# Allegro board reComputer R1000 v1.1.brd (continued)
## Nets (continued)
GND: C2.2 C3.2 C6.2 C7.2 C8.2 C9.2 C10.2 C11.2 C12.2 C13.2 C14.2 C15.2 C16.2 C19.2 C20.2 C21.2 C22.2 C23.2 C24.2 C28.2 C29.2 C31.2 C32.2 C33.1 C34.1 C35.1 C36.2 C37.2 C38.2 C40.2 C41.2 C42.2 C43.2 C44.2 C45.2 C46.2 C47.2 C48.2 C49.2 C50.2 C51.2 C52.2 C53.2 C54.2 C55.2 C56.2 C57.2 C58.2 C59.2 C60.2 C61.2 C62.2 C63.2 C64.2 C65.2 C66.2 C67.2 C68.2 C69.1 C70.1 C71.1 C72.1 C73.2 C74.2 C75.2 C76.1 C77.2 C78.1 C79.2 C80.2 C81.2 C82.2 C83.2 C84.2 C85.2 C86.2 C87.2 C88.2 C89.2 C90.2 C91.2 C92.2 C93.2 C94.2 C95.2 C96.2 C97.2 C98.2 C99.1 C100.1 C101.1 C102.1 C103.2 C104.2 C105.2 C106.2 C107.2 C108.2 C110.1 C111.2 C112.1 C113.1 C114.1 C115.1 C116.1 C117.2 C118.2 C119.2 C120.2 C121.2 C122.2 C123.2 C124.2 C125.2 C126.2 C127.2 C128.2 C130.2 C131.2 C132.2 C133.2 C136.2 C137.2 C139.2 C140.2 C142.2 C144.2 C145.2 C146.2 C150.2 C151.2 C152.2 C153.2 C159.1 C160.2 C161.2 C163.2 C164.2 C165.2 C166.2 C167.2 C168.2 C169.2 C499.2 C500.2 C501.2 C502.2 C503.2 C504.2 C505.1 C506.1 C507.1 D6.1 D7.1 D8.1 D10.1 D11.1 D12.1 D14.1 D15.1 D16.1 D17.1 D18.1 D19.1 D20.1 D21.1 D22.1 D23.1 D28.1 D30.1 D31.1 D32.1 D33.1 D61.1 D62.1 J2.7 J2.8 J2.9 J2.10 J4.1 J4.2 J4.7 J4.8 J4.13 J4.14 J4.22 J4.23 J4.32 J4.33 J4.42 J4.43 J4.52 J4.53 J4.59 J4.60 J4.65 J4.66 J4.71 J4.74 J4.98 J5.107 J5.108 J5.113 J5.114 J5.119 J5.120 J5.125 J5.126 J5.131 J5.132 J5.137 J5.138 J5.144 J5.150 J5.155 J5.156 J5.161 J5.162 J5.167 J5.168 J5.173 J5.174 J5.179 J5.180 J5.185 J5.186 J5.191 J5.192 J5.197 J5.198 J6.1 J6.4 J9.2 J9.5 J9.8 J9.11 J9.14(UTILITY) J9.17 J10.8 J11.A1 J11.A12 J11.B1 J11.B12 J12.1 J13.8 J14.4 J14.9 J14.15 J14.18 J14.21 J14.26 J14.27 J14.29 J14.34 J14.35 J14.37 J14.40 J14.43 J14.50 J14.53 J14.54 J15.9 J15.15 J15.18 J15.21 J15.26 J15.27 J15.29 J15.34 J15.35 J15.37 J15.40 J15.43 J15.50 J15.53 J15.54 J16.C5 J16.K2 J19.2 J19.4 J19.6 J19.8 J19.10 J19.12 J24.1 J24.4 J24.7 J24.10 J24.13 J24.16 J24.19 J24.SH1 J24.SH2 J24.SH3 J24.SH4 J25.10 J61.1 J61.2 J61.3 J61.5 J61.7 J61.8 J61.10 J61.12 J61.13 J62.1 J62.3 J62.9 J62.15 J62.21 J62.27 J62.33 J62.39 J62.45 J62.51 J62.57 J62.71 J62.73 J62.75 J62.76 J62.77 MH1.1(NC) MH2.1(NC) MH3.1(NC) MH4.1(NC) MH6.1(NC) MH7.1(NC) MH10.1(NC) OSC1.2 Q3.2(S) Q5.2(S) R7.2 R10.1 R12.2 R14.2 R17.1 R19.2 R21.2 R35.2 R37.2 R40.2 R42.1 R45.1 R48.2 R53.1 R54.1 R55.1 R56.1 R57.2 R58.2 R72.2 R73.2 R74.1 R75.1 R92.2 R93.2 R94.2 R95.2 R96.2 R97.2 R108.2 R119.2 R120.2 R123.1 R131.2 R138.2 R147.2 R161.1 R164.2 R173.2 R174.2 R573.2 R632.2 R633.2 R651.1 SW1.1 SW1.3 SW1.4 TP2.1(TP) TP3.1(TP) TP4.1(TP) TP5.1(TP) TP6.1(TP) TP7.1(TP) TP8.1(TP) TP9.1(TP) TP13.1(TP) TP17.1(TP) U1.7 U1.9 U2.7 U2.9 U3.4 U4.29 U4.30 U4.32 U4.34 U4.65 U5.37 U6.1 U7.6 U8.3 U8.8 U9.3 U9.8 U10.3 U10.8 U11.3 U11.8 U12.9 U12.25 U13.1(VSS) U14.4 U15.2 U15.17 U16.4 U17.1 U17.2 U17.3 U17.4 U18.3 U19.4 U19.9 U20.3 U20.8 U21.1(VSS) U22.1 U23.2 U24.2 U24.7 U24.8 U25.7 U25.11 U25.12 U25.13 U26.2 U26.7 U26.8 U27.2 U27.7 U27.8 U28.3(VOUT-) U29.3 U29.8 U30.3 U30.8 U31.2 U32.3 U32.8 U33.5 U34.3 U34.8 X1.2 X1.4 X2.2 X2.4
GND_EARTH: C158.2 C159.2 C505.2 C506.2 C507.2 G1.1 J3.1 J3.2 J3.3 J3.4 J8.S1 J8.S2 J8.S3 J8.S4 J9.20 J9.21 J9.22 J9.23 J10.13 J10.14 J11.S1 J11.S2 J11.S3 J11.S4 J18.13 J18.14 J25.S1 J25.S2 MH11.1(NC) MH12.1(NC) MH13.1(NC) MH14.1(NC) R161.2 R632.1 R633.1
GND_ISO: C134.2 C138.2 C141.2 C143.2 D34.1 D36.2 D39.1 D41.2 D44.1 D46.2 D48.1 J21.3 J22.3 J23.3 R123.2 R132.2 R141.2 R149.2 U22.3(VOUT-) U24.9 U24.10 U24.15 U26.9 U26.10 U26.15 U27.9 U27.10 U27.15
VCC_USB1: C76.2 C78.2 C82.1 C83.1 D16.2 FB5.1 U7.8
VCC_USB2: C77.1 C79.1 C84.1 C85.1 D17.2 FB6.2 U7.5(OUTB)
VDD18CORE: C6.1 C14.1 C19.1 U4.15 U4.38
VDD18ETHPLL: C502.1 FB3.1 U4.48
VDD18USBPLL: C501.1 FB3.2 U4.62
VDD33_HUB1: C40.1 C41.1 C43.1 C44.1 C45.1 C46.1 C47.1 C500.1 FB1.2 FB2.1 R41.1 R43.1 R44.1 R50.2 R78.1 R79.1 R80.1 R81.1 U4.19 U4.27 U4.33 U4.39 U4.40 U4.46 U33.8(VCC)
VDD33_HUB2: C59.1 C62.1 C63.1 C64.1 C65.1 C66.1 C67.1 C68.1 C73.1 FB4.2 R51.1 R52.1 R59.1 R60.2 R61.2 R62.2 R63.2 R65.2 R66.2 R67.2 R68.2 U5.5 U5.10 U5.15 U5.23 U5.29 U5.36 U6.4(VCC)
VDD33A_HUB1: C48.1 C49.1 C50.1 C51.1 C52.1 C53.1 C54.1 FB2.2 U4.5 U4.10 U4.49 U4.51 U4.54 U4.57 U4.64
VDD_3V3_PCIE: C166.1 C167.1 C168.1 C169.1 J62.2 J62.4 J62.12 J62.14 J62.16 J62.18 J62.70 J62.72 J62.74 OSC1.1 OSC1.4(VDD) R175.1 R176.2
VDD_3V3_SYS: C13.1 C23.1 C24.1 C30.1 C38.1 C42.1 C58.1 C89.1 C90.1 C91.1 C106.1 C107.1 C110.2 C163.1 C503.1 C504.1 D25.1 D27.1 FB1.1 FB4.1 FB9.1 FB26.2 FB27.2 J13.1 J13.7 L3.2 R38.1 R85.1 R88.1 R89.1 R90.1 R102.1 R113.1 R116.1 R176.1 R532.1 R653.1 R654.1 TP11.1(TP) U3.9(VCC) U12.21(VCC) U17.8 U19.8(VCC)
VDD_5V_OUT: C161.1 D62.2 J19.7 J19.9 J19.11 U31.1(OUT)
VDD_5V_OUT_CTL: R174.1 U12.12 U31.4
VDD_5V_SYS: C10.1 C11.1 C12.1 C17.1 C31.1 C80.1 C81.1 C108.1 C130.1 C131.1 D63.1 FB10.1 J4.77 J4.79 J4.81 J4.83 J4.85 J4.87 L2.2 R33.2 R104.1 R105.1 R652.1 TP10.1(TP) U7.7 U18.5 U23.5
VDD_IN: C7.1 C8.1 C9.1 C20.1 C21.1 C22.1 C162.1 D2.2(C) J2.2 J2.4 J2.6 Q4.1 Q4.2 Q4.3(S3) R8.1 R16.1 R162.1 TP1.1(TP) U1.2(VIN) U2.2(VIN)
VDD_LTE_3V3: C111.1 C115.2 C124.1 C125.1 C126.1 C127.1 J15.2 J15.39 J15.41 J15.52 R116.2 TP31.1(TP) U21.3
VDD_OUT: D61.2 J19.1 J19.3 J19.5 Q4.5 Q4.6 Q4.7 Q4.8 Q4.9
VDD_OUT_CTL: Q5.1 R164.1 U12.11
VDD_RTC: C104.1 C105.1 D27.2(C) D28.2 D29.2(C) TP22.1(TP) U16.8
VDD_UPS: D2.1 J2.1 J2.3 J2.5 Q1.5 Q1.6 Q1.7 Q1.8 Q1.9
CM4_GPIO24: J4.45 TP38.1(TP)
CM4_GPIO26: J4.24 TP39.1(TP)
CM4_GPIO27: J4.48 TP40.1(TP)
CM4_GPIO_VREF: C35.2 J4.78 R29.1 R30.1 R31.1 R106.1 R107.1 R177.1 R178.1 TP16.1(TP)
CM4_IIC0_SCL: J24.20 R27.1 R177.2 U19.6 U34.4 U34.7
CM4_IIC0_SDA: J24.21 R28.1 R178.2 U19.5 U34.5 U34.6(NC4)
CM4_IIC5_SCL: J61.9 R24.1 R30.2 R88.2 U12.19
CM4_IIC5_SDA: J61.11 R25.2 R31.2 R89.2 U12.20
CM4_IIC6_SCL: J2.11 J14.30 R23.2 R106.2 U16.6 U17.6
CM4_IIC6_SDA: J2.13 J14.32 R22.1 R107.2 U16.5 U17.5
CM4_SPI1_CE0: J4.49 J13.9
CM4_SPI1_CE1: J4.50 J14.51
CM4_SPI1_MISO: J4.26 J13.11 J14.47
CM4_SPI1_MOSI: J4.27 J13.12 J14.49
CM4_SPI1_SCLK: J4.25 J13.10 R111.1
CM4_TPM_IRQ: J4.29 J13.2
CM4_UART0_RXD: J4.51 R100.2
CM4_UART0_TXD: D26.2(C) J4.55 R99.2
CM4_UART2_CTS: J4.58 TP35.1(TP)
CM4_UART2_RTS: J4.56 R127.1
CM4_UART2_RXD: J4.35 R126.1
CM4_UART2_TXD: J4.36 R128.1
CM4_UART3_CTS: J4.30 TP36.1(TP)
CM4_UART3_RTS: J4.37 R136.1
CM4_UART3_RXD: J4.34 R134.1 U25.4
CM4_UART3_TXD: J4.54 R137.1 U25.5
CM4_UART4_CTS: J4.44 TP37.1(TP)
CM4_UART4_RTS: J4.38 R145.1
CM4_UART4_RXD: J4.40 R144.1 U25.9
CM4_UART4_TXD: J4.39 R146.1 U25.10
CM4_UPS_DET: J2.12 J4.41 R654.2
DSI1_C_N: J5.187 J24.8 U32.1 U32.10
DSI1_C_P: J5.189 J24.9 U32.2 U32.9
DSI1_D0_N: J5.175 J24.2 U20.1 U20.10
DSI1_D0_P: J5.177 J24.3 U20.2 U20.9
DSI1_D1_N: J5.181 J24.5 U20.4 U20.7
DSI1_D1_P: J5.183 J24.6 U20.5 U20.6(NC4)
DSI1_D2_N: J5.193 J24.11 U32.4 U32.7
DSI1_D2_P: J5.195 J24.12 U32.5 U32.6(NC4)
DSI1_D3_N: J5.194 J24.14 U34.1 U34.10
DSI1_D3_P: J5.196 J24.15 U34.2 U34.9
EECLK: U4.23 U33.2
EECS: R573.1 U4.24 U33.1
EEDI: U4.26 U33.4
EEDO: U4.25 U33.3
EEPROM_WP: R103.2 U12.10
ETHERNET_LED2: J4.17 R155.1
ETHERNET_LED3: J4.15 R160.1
ETHERNET_PAIR0_N: J4.10 T1.3 U29.2 U29.9
ETHERNET_PAIR0_P: J4.12 T1.1 U29.1 U29.10
ETHERNET_PAIR1_N: J4.6 T1.6 U29.5 U29.6(NC4)
ETHERNET_PAIR1_P: J4.4 T1.4 U29.4 U29.7
ETHERNET_PAIR2_N: J4.9 T1.9 U30.2 U30.9
ETHERNET_PAIR2_P: J4.11 T1.7 U30.1 U30.10
ETHERNET_PAIR3_N: J4.5 T1.12(TD4-) U30.5 U30.6(NC4)
ETHERNET_PAIR3_P: J4.3 T1.10 U30.4 U30.7
ETHERNET_RX_N: J10.3 R80.2 U4.53 U11.4 U11.7
ETHERNET_RX_P: J10.6 R81.2 U4.52 U11.5 U11.6(NC4)
ETHERNET_TX_N: J10.1 R78.2 U4.56 U11.1 U11.10
ETHERNET_TX_P: J10.2 R79.2 U4.55 U11.2 U11.9
EXT_RS485_1_A: D36.1 D37.2 J21.1 R125.2
EXT_RS485_1_B: D37.1 D39.2 J21.2 R130.2
EXT_RS485_2_A: D41.1 D42.2 J22.1 R135.2
EXT_RS485_2_B: D42.1 D44.2 J22.2 R140.2
EXT_RS485_3_A: D46.1 D47.2 J23.1 R143.2
EXT_RS485_3_B: D47.1 D48.2 J23.2 R150.2
EXT_VCC_9_36V: C1.1 C2.1 D1.2(C) L18.2 Q1.1 Q1.2 Q1.3(S3) Q2.2(E) R2.1 R3.1 R4.1
GLOBAL_EN: J4.99 U18.4(Y)
HDMI0_5V: C86.1 C87.1 D20.2 F2.1 J9.18
HDMI0_CEC: J5.151 J9.13 U10.1 U10.10
HDMI0_CLK_N: J5.190 L22.3
HDMI0_CLK_N1: J9.12 L22.4 U9.5 U9.6(NC4)
HDMI0_CLK_P: J5.188 L22.2
HDMI0_CLK_P1: J9.10 L22.1 U9.4 U9.7
HDMI0_HOTPLUG: J5.153 J9.19 U10.2 U10.9
HDMI0_SCL: J5.200 J9.15 U10.5 U10.6(NC4)
HDMI0_SDA: J5.199 J9.16 U10.4 U10.7
HDMI0_TX0_N: J5.184 L21.3
HDMI0_TX0_N1: J9.9 L21.4 U9.2 U9.9
HDMI0_TX0_P: J5.182 L21.2
HDMI0_TX0_P1: J9.7 L21.1 U9.1 U9.10
HDMI0_TX1_N: J5.178 L20.3
HDMI0_TX1_N1: J9.6 L20.4 U8.5 U8.6(NC4)
HDMI0_TX1_P: J5.176 L20.2
HDMI0_TX1_P1: J9.4 L20.1 U8.4 U8.7
HDMI0_TX2_N: J5.172 L19.3
HDMI0_TX2_N1: J9.3 L19.4 U8.2 U8.9
HDMI0_TX2_P: J5.170 L19.2
HDMI0_TX2_P1: J9.1 L19.1 U8.1 U8.10
IO_BUZZER_EN: R39.1 U12.15
ISO_5V: R117.1 U22.4
LORA_3V3: C112.2 C113.2 C114.2 C117.1 C118.1 C119.1 J14.2 J14.24 J14.39 J14.41 J14.52 R113.2 TP30.1(TP)
LORAWAN_SX1262_CS: J14.25 U12.1
LORAWAN_SX1262_RST: J14.10 U12.2
LORAWAN_SX1302_RST: R110.2 U12.3
LTE_RESET: R109.2 U12.4
NEXTRST: J4.100 R46.1
NLNKA_LED: R83.1 U4.21
NPIBOOT: J4.93 J6.2
NPWR_LED: J4.95 J25.1
NSPD_LED: R84.1 U4.22
PCIE_CLK_N: J5.112 J62.53
PCIE_CLK_NREQ: J5.102 J62.52
PCIE_CLK_P: J5.110 J62.55
PCIE_NRST: J5.109 J62.50
PCIE_RX_N: J5.118 J62.41
PCIE_RX_P: J5.116 J62.43
PCIE_TX_N: J5.124 J62.47
PCIE_TX_P: J5.122 J62.49
PCIE_USIM_PRESE: J15.44 J16.K1 R114.2
PL_NLED: J4.21 J25.2
POE_12V: C144.1 C145.1 C146.1 D1.1 TP34.1(TP) U28.1 U28.2
POE_IN_N: C148.2 C149.2 D50.1 D51.2 D52.2 L16.1
POE_IN_N1: C147.1 L16.4 U28.7 U28.8
POE_IN_P: C149.1 D51.1 D52.1 L15.2
POE_IN_P1: C147.2 L16.3 U28.5 U28.6
RS485_1_A: R124.2 R125.1 R129.1 U24.12
RS485_1_B: R129.2 R130.1 R132.1 U24.13
RS485_2_A: R133.2 R135.1 R139.1 U26.12
RS485_2_B: R139.2 R140.1 R141.1 U26.13
RS485_3_A: R142.2 R143.1 R148.1 U27.12
RS485_3_B: R148.2 R149.1 R150.1 U27.13
RS485_LED1: J25.6 U25.3
RS485_LED2: J25.7 U25.6
RS485_LED3: J25.8 U25.8
RS485_POWER_EN: R122.1 U12.14
RTC_INT: C109.1 R104.2 U16.3
RUN_PG: J4.92 R36.2
SD_VDD_OVERRIDE: J4.73 R26.1
TPM_RST: J13.3 U12.5
TRCT: C88.1 J10.4 J10.5 J10.9 J10.12 R82.2
UART2_RXD: R126.2 U24.3 U25.1
UART2_TXD: R128.2 U24.6 U25.2
UART_3V3: C97.1 C100.2 D24.1 R96.1 R98.1 TP21.1(TP) U13.2 U15.1(VIO)
USB1_RST: C55.1 R44.2 R46.2 R64.1 U4.12
USB2_RST: C61.1 R52.2 R59.2 R71.2 U5.26 U6.2
USB2_RST_EN: R71.1 U12.13
USB2_VBUS_EN1: R65.1 R75.2 U5.12 U7.1
USB2_VBUS_EN2: R66.1 R74.2 U5.16 U7.4
USB2_VRCURN1: R60.1 U5.13 U7.2
USB2_VRCURN2: R61.1 U5.17 U7.3
USB_0M: U3.7 U4.58
USB_0P: U3.1 U4.59
USB_1M: U3.6 U14.6
USB_1P: U3.2 U14.2
USB_C_DM: R530.2 U14.5
USB_C_DP: R531.2 U14.3
USB_DET: C60.1 R51.2 U5.27
USB_DM: J5.103 U3.5
USB_DP: J5.105 U3.3
USB_HUB1_DM2: J61.6 U4.1
USB_HUB1_DM3: U4.3 U5.30
USB_HUB1_DP2: J61.4 U4.2
USB_HUB1_DP3: U4.4 U5.31
USB_HUB2_DM1: L4.4 U5.1
USB_HUB2_DM2: L5.2 U5.3
USB_HUB2_DM3: J14.36 U5.6
USB_HUB2_DM4: J15.36 U5.8
USB_HUB2_DP1: L4.1 U5.2
USB_HUB2_DP2: L5.3 U5.4
USB_HUB2_DP3: J14.38 U5.7
USB_HUB2_DP4: J15.38 U5.9
USB_OTG_ID: C37.1 J5.101 R34.2 R35.1 U3.10 U14.10
USB_OTG_ID1: J6.5(COM2) R34.1
USB_TO_UART_DM: U14.7 U15.8
USB_TO_UART_DP: U14.1 U15.7
USBA_GND: J8.A4 J8.B4 R72.1 R73.1
USBC_DM: D23.2 J11.A7 J11.B7 R530.1
USBC_DP: D22.2 J11.A6 J11.B6 R531.1
USER_LED_B: J25.4 U12.8
USER_LED_G: J25.3 U12.7
USER_LED_R: J25.5 U12.6
USIM_1V8: C116.2 R112.1 R114.1 TP29.1(TP) U21.2
USIM_CLK: C123.1 D31.2 J15.12 J16.C3
USIM_DATA: C122.1 D30.2 J15.10 J16.C7 R115.2
USIM_GND: J15.4 R108.1
USIM_RST: C128.1 D32.2 J15.14 J16.C2
USIM_VDD: C120.1 C121.1 D33.2 J15.8 J16.C1 R115.1
VETH_DVDDH: C160.1 FB9.2 J18.10 J18.12 R82.1
N17790331: J4.31 R25.1
N17790840: J4.89(WL_NDISABLE) TP14.1(TP)
N17790854: J4.91 TP15.1(TP)
N18106868: J4.19 TP12.1(TP)
N21083178: D29.1 J12.2 TP23.1(TP)
N21084468: C109.2 R105.2 U18.2
N21116206: F1.1 J1.1 R182.1
N21116211: D4.1 D5.1 D7.2(C) J1.2 R183.2
N21116390: D3.1 D5.2 D6.2(C) F1.2
N21149713: J14.14 TP25.1(TP)
N21149734: J14.16 TP26.1(TP)
N21149896: J14.31 TP27.1(TP)
N21149903: J14.33 TP28.1(TP)
N21150017: J14.45 R111.2
N21187983: D8.2(C) R2.2 R5.1
N21187993: Q2.1 R5.2
N21188161: D9.1 Q2.3
N21188625: C1.2 D9.2(C) Q1.4 R3.2 R7.1
N21206327: C103.1 R101.2 U16.1 X3.2
N21206924: C102.2 R101.1 U16.2(X2) X3.1
N21339151: J14.22 R110.1
N21339355: J15.22 R109.1
N21392725: C36.1 J6.6 R32.1 R33.1
N21411651: C133.1 L11.2 U22.2
N21411770: D34.2(C) R118.2 TP33.1(TP)
N21419586: R127.2 R131.1 U24.4(\\R\E) U24.5
N21629438: C3.1 R4.2
N21664516: R37.1 U3.8
N21891930: C56.1 R47.1 R49.1 X1.1
N21894342: C57.1 R49.2 U4.60(XO) X1.3
N22026897: J18.1 T1.24
N22026906: J18.2 T1.22
N22026915: J18.3 T1.21
N22026957: J18.7 T1.15
N22026966: J18.8 T1.13
N22027038: R153.2 R159.1 T1.14
N22027110: R151.2 R157.1 T1.20
N22027117: R154.2 R158.1 T1.17
N22027433: J18.11(YELC) R155.2
N22027462: J18.9 R160.2
N22028382: R152.2 R156.1 T1.23
N22028488: D52.4 R153.1
N22028491: D52.3(~2) R154.1
N22029929: C148.1 D50.2 L15.1 L16.2
N22030276: D51.4 R151.1
N22030277: D51.3(~2) R152.1
N22038029: C154.1 R156.2
N22038032: C154.2 C155.2 C156.2 C157.2 C158.1
N22038068: C155.1 R157.2
N22038120: C156.1 R158.2
N22038172: C157.1 R159.2
N22078660: J18.6 T1.19
N22078676: J18.5 T1.16
N22078685: J18.4 T1.18
N22567639: C153.1 T1.11
N22567644: C152.1 T1.8
N22567654: C151.1 T1.5
N22567659: C150.1 T1.2
N22666345: R119.1 R122.2 U23.4
N22666568: R120.1 U23.3
N22695835: J14.8 TP24.1(TP)
N22714565: R102.2 R103.1 U17.7(WP)
N23370571: R41.2 U4.11
N23400557: R42.2 U4.63
N23401903: R43.2 U4.41
N23402124: R45.2 U4.50
N23405519: R47.2 U4.61
N23430020: R134.2 U26.3
N23430038: R136.2 R138.1 U26.4(\\R\E) U26.5
N23430129: R137.2 U26.6
N23431044: R144.2 U27.3
N23431062: R145.2 R147.1 U27.4(\\R\E) U27.5
N23431153: R146.2 U27.6
N23449459: J11.A5 R94.1
N23449477: J11.B5 R95.1
N23449775: C98.1 D24.2(C) D25.2(C) U14.9(VCC)
N23449933: D26.1 R98.2 R99.1 U15.5
N23449979: C101.2 U15.6
N23450082: R100.1 U15.4
N23450096: R97.1 U14.8
N23451512: R53.2 U5.28
N23451530: R54.2 U5.22
N23451550: R55.2 U5.24
N23451563: R56.2 U5.25
N23451623: R57.1 U5.11
N23451671: R58.1 U5.35
N23451839: C69.2 C70.2 U5.34
N23451845: R62.1 U5.19
N23451875: C71.2 C72.2 U5.14
N23451879: R63.1 U5.21
N23451944: R69.2 U5.32(XTALOUT)
N23451981: R67.1 U5.18
N23452005: C75.1 R70.2 U5.33 X2.3
N23452009: R68.1 U5.20
N23452027: C74.1 R69.1 R70.1 X2.1
N23452929: FB6.1 J8.B1(VBUS_B)
N23452966: D18.2 J8.B2 L5.1
N23452985: D19.2 J8.B3 L5.4
N23455465: D12.2 R36.1 SW1.2
N23456906: R64.2 U6.3
N23459666: R50.1 U4.28
N23461225: R48.1 U4.44
N23461314: TP19.1(TP) U4.45
N23463209: J10.10 R83.2
N23463212: J10.11(YELC) R84.2
N23463479: TP18.1(TP) U4.20
N23466024: R85.2 U12.18
N23466034: R90.2 U12.22
N23466170: R92.1 U12.23
N23466179: R93.1 U12.24
N23473877: B1.1 D13.2(C) R38.2
N23473909: B1.2(-) D13.1 Q3.3
N23473945: Q3.1 R39.2 R40.1
N23500588: J62.68(SUSCLK(32KHZ) (O)(0/3.3V)) OSC1.3
N23502047: J62.54 R175.2
N23514160: J4.46 R22.2
N23514205: J4.47 R23.1
N23529653: J4.80 R27.2
N23529656: J4.82 R28.2
N23572410: C162.2 Q4.4 R162.2 R163.2
N23572413: Q5.3 R163.1
N23572753: C164.1 C165.1 FB10.2 U31.5
N23578952: R173.1 U31.3
N23579284: C499.1 D3.2(C) D4.2(C) L18.1
N23611485: R12.1 U1.4
N23611490: C15.1 U1.6
N23612078: C5.1 U1.1
N23612081: C5.2 R9.1
N23613464: D10.2(C) L2.1 R9.2 R11.1 U1.8
N23613978: R8.2 R10.2 U1.3
N23614867: C17.2 R13.2 R14.1 U1.5
N23615765: C16.1 R11.2
N23616333: C18.1 U2.1
N23616335: C18.2 R15.1
N23616337: D11.2(C) L3.1 R15.2 R18.1 U2.8
N23616378: R16.2 R17.2 R181.2 U2.3
N23616505: R19.1 U2.4
N23616509: C30.2 R20.2 R21.1 U2.5
N23616593: C28.1 U2.6
N23616615: C29.1 R18.2
N23711005: D15.2 J8.A2 L4.3
N23711301: D14.2 J8.A3 L4.2
N23763799: G1.2 R182.2 R183.1
N23781625: R651.2 U33.6
N23800931: R13.1 R652.2
N23801005: R20.1 R653.2
N23858113: FB26.1 J24.22
N23860408: FB27.1 J25.9
N23869571: D63.2(C) F2.2
N23912708: J4.28 R24.2
N234528750: FB5.2 J8.A1

Pads without a net: J4 16 18 20 57 61 62 63 64 67 68 69 70 72 75 76 94 96 97; J5 104 106 111 115 117 121 123 127 128 129 130 133 134 135 136 139 140 141 142 143 145 146 147 148 149 152 154 157 158 159 160 163 164 165 166 169 171; J6 3; J10 7; J13 4 5 6 13; J14 1 3 5 6 7 11 12 13 17 19 20 23 28 42 44 46 48; J15 1 3 5 6 7 11 13 16 17 19 20 23 24 25 28 30 31 32 33 42 45 46 47 48 49 51; J16 C6; J19 13; J24 17 18; J62 5 6 7 8 10 11 13 17 19 20 22 23 24 25 26 28 29 30 31 32 34 35 36 37 38 40 42 44 46 48 56 58 67 69; U4 6 7 8 9 13 14 16 17 18 31 35 36 37 42 43 47; U12 16 17; U15 10 11 12 13 14 15 16; U16 7; U18 1; U19 1 2 3 7; U24 11 14; U26 11 14; U27 11 14; U28 4; U33 7

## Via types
v1: diameter 0.406, hole 0.203, TOP to BOTTOM, 1791 vias
v2: diameter 0.457, hole 0.203, TOP to BOTTOM, 4 vias

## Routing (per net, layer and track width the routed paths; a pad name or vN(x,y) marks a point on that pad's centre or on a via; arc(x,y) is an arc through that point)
3V3_RS485: length 79.6
  TOP w0.305: C139.1 v1(37.46,56.85) 37.46,57.35 37.37,57.43 U25.14
  LYR3 w0.508: v1(37.46,56.85) 39.96,54.36 39.96,52.64 35.94,48.63 32.46,48.63 31.19,47.36 31.19,43.27 32.77,41.69 32.77,30.59 35.23,28.13 v1(35.23,26.33)
  LYR6 w0.508: v1(62.38,25.34) 62.28,25.23 58.02,25.23 55.73,22.95 49.67,22.95 48.06,24.56 41.65,24.56 39.88,26.33 v1(35.23,26.33)
  BOTTOM w0.305: U27.1 62.69,24.88 62.84,25.03 C142.1 ; C142.1 v1(62.84,25.72) ; C142.1 v1(62.38,25.34) ; U24.1 84.67,24.46 85.07,24.85 C137.1 83.9,25.31 83.7,25.11 v1(83.7,24.19) ; v1(72.64,24.52) 73.43,25.31 C140.1 74.07,24.93 73.71,24.57 U26.1
  vias: v1(62.87,26.78)
5V_ISO_OUT: length 14.3
  TOP w0.305: v1(84.69,15.3) 85.06,14.93 C138.1 ; C141.1 74.04,15.05 v1(73.74,15.35) ; C143.1 62.74,13.15 v1(62.59,13.3) ; R118.1 v1(64.59,17.05)
  TOP w0.508: R124.1 v1(92.36,16.32) ; R133.1 v1(79.83,9.54) ; R142.1 72.8,10.76 72.44,10.4 v1(72.44,9.77)
  BOTTOM w0.305: v1(73.74,15.35) 73.74,14.33 U26.16 ; v1(62.59,13.3) 62.69,13.4 U27.16 ; U24.16 84.69,14.31 v1(84.69,15.3)
  BOTTOM w0.508: v1(92.36,16.32) 94.21,16.32 TP32.1
  vias: v1(66.93,12.97) v1(67.36,12.99) v1(67.82,12.99)
5V_TYPC: length 3
  TOP w0.254: U15.9 v1(39.03,53.69) ; 34.6,54.52 34.92,54.19 U15.3
  TOP w0.508: C99.2 34.31,55.19 v1(34.37,55.13) 34.39,55.11 34.39,54.73 34.6,54.52
  vias: v1(10.7,35.78) v1(11.15,35.78) v1(28.04,37.91) v1(28.07,37.45) v1(28.53,37.91) v1(28.55,37.45) v1(33.89,22.9) v1(33.89,22.39) v1(34.37,22.9) v1(34.37,22.39) v1(60.07,3.16) v1(60.07,2.7) v1(60.51,2.7) v1(61.01,12.66) v1(61.01,12.23) v1(61.45,12.23) v1(61.8,10.12) v1(62.23,10.12) v1(62.23,9.66)
+1.8V_OUT: length 1.4
  TOP w0.203: J4.88 56.6,72.21 v1(56.52,72.12) ; v1(56.16,71.87) 56.2,71.91 J4.90
+3.3V_OUT: length 52.4
  TOP w0.305: v1(59.44,79.84) 59.47,79.88 C32.1 R26.2
  LYR3 w0.305: v1(59.44,79.84) 59.44,78.9 58.06,77.52 v1(58.06,74.87) ; v1(58.02,37.88) 57.69,38.21 57.69,52.06 58.91,53.28 58.91,60.64 57.69,61.86 57.69,66.66 53.72,70.63 53.72,72.55 53.98,72.81 56.9,72.81 57.2,72.5 v1(57.2,72.07)
  BOTTOM w0.254: v1(58.02,37.88) 58.1,37.8 58.1,37.42 R181.1
  BOTTOM w0.305: v1(58.06,74.87) R29.2 57.62,73.29 C33.2 57.23,72.1 v1(57.2,72.07)
GND: length 1120.8
  TOP w0.203: U4.30 47.84,35.87 47.86,35.85 ; 45.39,34.99 45.38,35 45.38,35.33 45.53,35.48 U4.34 46.93,35.48 47.09,35.32 ; 70.08,38.13 70.2,38.25 J5.120 70.2,39.52 70.21,39.52 ; J5.186 v1(57,37.82) ; J5.174 v1(59.4,38.15) ; v1(69.19,42.48) 69,42.29 J5.125 69,40.54 68.99,40.52 ; v1(61.83,41.22) 62.89,41.22 63,41.33 J5.155 63,42.38 ; v1(61.83,41.22) 61.8,41.24 J5.161 61.8,42.57 v1(61.8,42.57) ; v1(61.83,41.22) 60.66,41.22 ; C102.1 8.89,70.24 v1(8.91,70.22) ; J4.7 72.6,74.9 v1(72.6,74.89) ; 67.8,41.06 67.8,41.07 J5.131 67.8,42.52 67.67,42.66 ; J4.43 65.4,76.18 65.48,76.26 65.48,77.3 v1(65,77.79) ; v1(47.27,35.93) 47.09,35.93 46.84,36.18 U4.32 ; 67.19,8.77 68.51,8.77 v1(68.53,8.75) ; J5.107 v1(72.6,42.57) ; 60.66,41.22 60.6,41.27 J5.167 60.6,42.53 ; 60.66,41.22 59.49,41.22 ; v1(72.6,72.05) 72.6,72.05 J4.8 72.6,73.18 72.37,73.42 ; J4.53 v1(63.4,76.44) ; 59.49,41.22 59.4,41.31 J5.173 59.4,42.7 59.39,42.71 ; 59.49,41.22 58.24,41.22 v1(58.2,41.25) ; J5.113 v1(71.4,42.55) ; v1(70.26,43.06) 70.2,43.01 J5.119 70.2,41.41 69.93,41.13 69.9,41.13 ; J4.66 61,72.14 v1(60.99,72.12) ; 54.51,42.63 54.6,42.54 J5.197 54.6,41.32 54.59,41.3 54.67,41.22 55.73,41.22 ; v1(58.2,41.25) J5.179 58.2,42.69 58.22,42.71 ; v1(58.2,41.25) 58.17,41.22 57,41.22 ; v1(58.2,41.25) J5.180 ; 55.73,41.22 55.8,41.29 J5.191 55.8,42.59 55.73,42.66 ; 55.73,41.22 57,41.22 ; v1(69.52,76.47) 69.4,76.35 J4.23 ; 55.76,39.43 55.8,39.39 J5.192 55.8,37.94 55.73,37.87 ; v1(68.2,39.81) 67.8,39.41 J5.132 67.8,38 67.82,37.98 ; J4.71 59.8,75.15 59.84,75.11 ; 64.11,37.87 64.2,37.96 J5.150 ; U12.9 30.65,70.36 v1(30.38,70.62) ; 57,41.22 57,41.3 57,41.3 J5.185 57,42.46 57.08,42.53 v1(57.08,42.63) ; J4.65 61,75.17 v1(61.01,75.16) ; 68.99,37.96 69,37.97 J5.126 69,39.9 v1(69.04,39.94) ; C48.2 58.04,25.46 v1(58.37,25.79) ; v1(66.6,37.35) J5.138 66.6,39.58 ; 65.36,39.66 65.4,39.62 J5.144 65.4,37.76 65.41,37.76 ; X1.2 52.18,25.59 v1(52.17,25.59) ; 60.68,38.13 60.6,38.21 J5.168 ; J4.32 67.8,73.42 66.97,74.26 66.73,74.26 v1(66.58,74.41) ; C49.2 55.47,25.34 R42.1 ; J4.1 73.8,76.35 v1(73.81,76.36) ; U3.4 v1(60.28,31.13) ; v1(62.03,73.29) 62.18,73.29 62.2,73.27 J4.60 ; J5.198 54.6,39.37 54.69,39.46 ; J4.22 69.8,73.42 69.75,73.47 v1(69.7,73.47) ; J4.13 71.4,78.63 MH6.1 ; 66.58,40.88 66.6,40.91 J5.137 66.6,42.71 66.47,42.84 65.1,42.84 v1(65.05,42.79) ; v1(71.38,73.44) 71.4,73.42 J4.14 71.4,71.92 71.38,71.89 ; J4.33 67.4,75.41 67.41,75.4 v1(67.41,75.2) ; v1(61.7,38) 61.8,38.1 J5.162 ; v1(59.44,72.1) 59.4,72.13 J4.74 ; v1(54.36,73.39) 54.6,73.15 J4.98 ; J5.156 63,38.29 v1(62.84,38.13) ; J5.108 72.6,38.25 v1(72.21,37.86) ; J4.59 62.2,75.23 v1(62.13,75.16) ; v1(71.4,37.85) J5.114 ; J4.42 65.8,73.36 65.97,73.52 ; 48.36,35.8 48.34,35.83 U4.29 ; J4.52 63.8,73.22 63.6,73.42 ; J4.2 v1(73.8,72.11)
  TOP w0.254: 36.14,56.87 36.07,56.95 U25.12 ; v1(7.22,69.81) 7.21,69.82 C103.2 ; C55.2 57.51,34.48 57.76,34.22 v1(57.76,33.92) ; U15.2 36.64,54.69 U15.17 36.89,53.97 v1(36.88,53.96) ; C139.2 36.59,57.25 36.72,57.38 U25.13 ; C101.1 v1(36.66,50.59) ; C57.2 v1(52.17,25.59) C50.2 ; v1(35.66,56.88) 35.66,56.87 C100.1 35.31,57 35.42,57.11 U25.11 ; v1(32.18,54.55) 32.17,54.53 C128.2 ; v1(46.41,25.26) 46.5,25.17 R45.1 ; v1(60.12,9.99) 60.45,9.67 D23.1 ; C54.2 v1(57.27,30.93) ; C14.2 44.34,33.6 v1(44.22,33.49) 44.34,33.37 C46.2 ; C43.2 43.64,35.22 43.89,34.96 v1(43.89,34.86) ; v1(44.78,34.81) C41.2 ; R48.2 v1(44.34,31.01) ; C56.2 v1(53.67,25.21)
  TOP w0.305: v1(102.49,71.03) 102.95,71.03 103.29,70.69 R74.1 ; C128.2 32.38,53.95 D31.1 32.38,52.75 C123.2 32.17,52.38 31.84,52.06 30.76,52.06 27.08,48.37 v1(27.08,46.19) ; R57.2 C59.2 v1(101.21,74.53) ; v1(32.34,69.38) 32.54,69.17 C116.1 v1(32.73,69.6) 32.73,69.6 C110.1 ; v1(60.1,12.13) 60.45,11.78 C92.2 60.45,11.08 v1(60.38,11.01) ; C67.2 v1(97.92,74.41) ; 78.64,35.83 v1(78.64,36.26) 78.87,36.03 C125.2 ; v1(32.38,55.5) 32.17,55.71 C121.2 C120.2 32.38,56.94 D33.1 ; v1(34.67,66.53) 34.64,66.56 U21.1 34.38,67.51 v1(33.95,67.51) ; v1(32.18,54.55) 32.38,54.74 D32.1 ; R131.2 v1(75.59,19.52) ; v1(102.06,49.08) U10.3 U10.8 ; 68.53,8.74 v1(68.53,8.75) ; 68.53,8.74 R94.2 ; 68.53,8.74 R95.2 ; 8.74,71.94 7.52,71.94 v1(7.04,71.46) ; R37.2 C38.2 60.56,26.05 v1(60.38,25.87) ; R147.2 65.74,24.81 v1(65.84,24.9) ; v1(49.25,24.22) 49.05,24.01 U11.3 U11.8 ; C90.2 v1(25.99,71.38) C91.2 v1(25.23,71.38) ; v1(74.25,22.85) 74.02,23.07 R119.2 ; R93.2 R92.2 25.51,69.32 v1(25.38,69.46) ; v1(46.41,25.26) 46.21,25.45 C53.2 ; 36.14,56.87 v1(36.17,56.85) C139.2 ; v1(71.53,24.95) 71.73,24.75 C131.2 ; v1(103.18,71.64) 103.29,71.76 R75.1 ; v1(57,37.82) 57.9,36.92 C19.2 57.73,36.6 57.22,36.09 C47.2 ; v1(75.34,20.51) 75.59,20.76 R138.2 ; C74.2 100.16,64.98 v1(100.21,64.93) ; C112.1 70.18,36.44 v1(69.9,36.71) ; C93.2 61.9,13.14 61.69,13.36 60.34,13.36 v1(60.05,13.07) ; R7.2 101.99,36.91 v1(101.93,36.97) ; R120.2 v1(74.5,17.16) ; v1(35.36,66.48) 35.39,66.51 C115.1 ; R53.1 96.3,64.69 v1(96.37,64.76) 96.44,64.69 C63.2
  TOP w0.375: MH4.1 93.81,73.75 ; MH4.1 90.5,70.45 ; MH4.1 90.5,77.06 ; MH4.1 87.2,73.75 ; 11.22,74.91 D28.1 ; D28.1 10.72,75.41 ; D28.1 11.22,75.92 ; 44.33,26.71 C502.2 ; C502.2 44.84,27.22 ; C502.2 43.83,27.22 ; C104.2 11.22,74.89 ; C104.2 10.72,74.38 ; C104.2 11.22,73.88 ; v1(50.59,32.23) 50.59,34.98 ; v1(50.59,32.23) 53.34,32.23 ; v1(50.59,32.23) 47.83,32.23 ; v1(50.59,32.23) 50.59,29.47 ; U22.1 59.75,23.38 ; U22.1 59.04,24.34 ; U22.1 58.34,23.38 ; 94.41,64.69 C64.2 95.23,64.69 ; R164.2 26.44,78.63 ; R164.2 26.44,77.81 ; R164.2 26.05,78.22 ; 25.45,68.53 R93.2 25.84,68.12 ; 19.65,3.09 J25.10 19.65,4.8 ; 102.12,65.56 C75.2 102.63,65.05 ; 103.71,72.01 R75.1 102.88,72.01 ; 33.02,64.04 U25.7 33.47,63.19 ; J12.1 12.15,82.05 ; J12.1 12.15,80.54 ; J12.1 12.9,81.3 ; 5.03,29.28 J6.4 ; J6.4 6.04,30.28 ; J6.4 5.03,31.29 ; 61.88,7.03 C97.2 61.38,6.53 ; 43.94,34.06 C14.2 44.34,34.47 ; MH6.1 71.94,81.62 ; MH6.1 69.49,79.17 ; MH6.1 74.4,79.17 ; MH6.1 71.94,76.71 ; 25.71,76.9 Q5.2 ; Q5.2 26.47,76.07 ; Q5.2 27.23,76.9 ; 109.07,71.22 U7.6 ; U7.6 110.1,70.66 ; U7.6 110.1,71.77 ; U7.6 111.13,71.22 ; C501.2 43.49,24.75 ; C501.2 42.67,24.75 ; C501.2 43.08,24.36 ; 61.8,4.8 U13.1 ; U13.1 61.8,6.45 ; U13.1 61.04,5.62 ; 53.56,22.38 X1.4 54.48,23.16 ; J16.C5 5.31,57.2 ; J16.C5 2.5,57.2 ; J16.C5 3.9,58.16 ; J16.C5 3.9,56.25 ; 102.76,62.78 X2.2 ; X2.2 102.76,64.61 ; X2.2 103.54,63.69 ; X2.2 101.97,63.69 ; SW1.3 6,22.18 ; SW1.3 6,19.57 ; SW1.3 7.3,20.88 ; SW1.3 4.69,20.88 ; U28.3 11.01,41.58 ; U28.3 12.27,40.33 ; U28.3 11.01,39.07 ; U28.3 9.75,40.33 ; 25.7,44.83 J16.K2 ; J16.K2 27.1,43.88 ; J16.K2 28.51,44.83 ; 90.5,37.45 MH3.1 ; MH3.1 87.2,40.75 ; MH3.1 90.5,44.06 ; J10.8 55.14,18.06 ; J10.8 54.08,16.99 ; J10.8 54.08,19.13 ; J10.8 53.01,18.06 ; 98.99,48.09 D20.1 99.5,47.59 ; 47.1,23.53 C88.2 47.61,23.03 ; 32.38,58.17 D33.1 32.88,57.67 ; 110.32,41.24 J9.2 111.03,41.94 ; 100.91,60.48 X2.4 101.69,61.39 ; 42.5,77.06 MH1.1 45.81,73.75 ; 24.48,68.64 C89.2 ; C89.2 24.98,69.15 ; C89.2 23.98,69.15 ; SW1.1 4.85,15.03 ; SW1.1 3.55,13.72 ; SW1.1 3.55,16.33 ; 38.18,71.63 U19.4 37.57,72.01 ; 43.95,29.56 C45.2 44.34,29.14 ; 93.96,60.69 MH7.1 97.16,57.48 ; C87.2 99.49,48.92 ; C87.2 98.99,48.42 ; C87.2 98.99,49.43 ; 4.69,13.68 SW1.4 ; SW1.4 7.3,13.68 ; SW1.4 6,14.98 ; U16.4 10.51,69.04 ; U16.4 10.51,67.94 ; U16.4 11.54,68.49 ; 14.7,74.8 C105.2 15.09,74.39 ; 57.28,32.12 C51.2 57.67,32.54 ; MH2.1 42.5,44.06 ; MH2.1 39.2,40.75 ; MH2.1 45.81,40.75 ; MH2.1 42.5,37.45 ; 59.38,80.39 C32.2 59.79,80.78 ; 104.04,76.71 MH10.1 106.5,79.17 ; 58.93,32.65 C119.2 59.34,33.05
  TOP w0.381: v1(60.3,37.05) 59.77,37.05 59.69,36.97 C6.2
  TOP w0.508: D22.1 v1(59.97,8) ; v1(27.08,46.19) 27.1,46.17 J16.K2 ; C99.1 v1(33.02,56.72) ; D32.1 v1(32.38,55.5)
  LYR2_GND w0.254: 105.11,43.95 105.13,43.94 J9.11 ; 107.77,43.62 107.88,43.62 108.56,42.94 J9.5 ; v1(106.25,41.24) 106.35,41.24 106.86,41.74 J9.8 ; v1(102.77,41.26) 103.39,41.88 J9.14 ; 101.78,43.85 101.66,43.73 J9.17
  LYR2_GND w0.375: 3.55,13.72 SW1.1 ; SW1.1 3.55,16.33 ; SW1.1 4.85,15.03 ; 104.04,75.96 MH10.1 107.25,79.17 ; MH2.1 45.81,40.75 ; MH2.1 42.5,37.45 ; MH2.1 42.5,44.06 ; MH2.1 39.2,40.75 ; 90.5,37.45 MH3.1 ; MH3.1 87.2,40.75 ; MH3.1 90.5,44.06 ; MH3.1 93.81,40.75 ; 12.15,80.54 J12.1 ; J12.1 12.9,81.3 ; J12.1 12.15,82.05 ; MH7.1 97.16,63.89 ; MH7.1 100.37,60.69 ; MH7.1 97.16,57.48 ; MH7.1 93.96,60.69 ; MH4.1 93.81,73.75 ; MH4.1 87.2,73.75 ; MH4.1 90.5,70.45 ; MH4.1 90.5,77.06 ; 9.75,40.33 U28.3 ; U28.3 11.01,39.07 ; U28.3 11.01,41.58 ; U28.3 12.27,40.33 ; 68.74,79.17 MH6.1 ; MH6.1 71.94,75.96 ; MH6.1 71.94,82.37 ; MH6.1 75.15,79.17 ; 5.03,29.28 J6.4 ; J6.4 5.03,31.29 ; J6.4 6.04,30.28 ; SW1.3 6,22.18 ; SW1.3 4.69,20.88 ; SW1.3 7.3,20.88 ; SW1.3 6,19.57 ; 111.03,41.94 J9.2 110.32,41.24 ; SW1.4 7.3,13.68 ; SW1.4 4.69,13.68 ; SW1.4 6,14.98 ; U22.1 59.75,23.38 ; U22.1 58.34,23.38 ; U22.1 59.04,24.34 ; 39.2,73.75 MH1.1 ; MH1.1 45.81,73.75 ; MH1.1 42.5,70.45 ; MH1.1 42.5,77.06 ; J10.8 55.14,18.06 ; J10.8 53.01,18.06 ; J10.8 54.08,19.13 ; J10.8 54.08,16.99
  LYR3 w0.508: v1(4.52,36.69) 3.24,36.69 J6.1
  LYR4_GND w0.375: U28.3 11.01,41.58 ; U28.3 12.27,40.33 ; U28.3 11.01,39.07 ; U28.3 9.75,40.33 ; 39.2,40.75 MH2.1 ; MH2.1 42.5,37.45 ; MH2.1 45.81,40.75 ; MH2.1 42.5,44.06 ; SW1.3 7.3,20.88 ; SW1.3 4.69,20.88 ; SW1.3 6,19.57 ; MH1.1 42.5,77.06 ; MH1.1 39.2,73.75 ; MH1.1 42.5,70.45 ; MH1.1 45.81,73.75 ; 53.01,18.06 J10.8 ; J10.8 54.08,16.99 ; J10.8 54.08,19.13 ; J10.8 55.14,18.06 ; 87.2,40.75 MH3.1 ; MH3.1 93.81,40.75 ; MH3.1 90.5,37.45 ; MH3.1 90.5,44.06 ; MH4.1 90.5,77.06 ; MH4.1 93.81,73.75 ; MH4.1 87.2,73.75 ; MH4.1 90.5,70.45 ; J12.1 12.15,82.05 ; J12.1 12.15,80.54 ; J12.1 12.9,81.3 ; 107.25,79.17 MH10.1 104.04,75.96 ; MH7.1 100.37,60.69 ; MH7.1 97.16,57.48 ; MH7.1 93.96,60.69 ; MH7.1 97.16,63.89 ; 110.32,41.24 J9.2 111.03,41.94 ; SW1.4 7.3,13.68 ; SW1.4 4.69,13.68 ; SW1.4 6,14.98 ; 68.74,79.17 MH6.1 ; MH6.1 71.94,75.96 ; MH6.1 71.94,82.37 ; MH6.1 75.15,79.17 ; J6.4 5.03,31.29 ; J6.4 5.03,29.28 ; J6.4 6.04,30.28 ; U22.1 59.75,23.38 ; U22.1 58.34,23.38 ; U22.1 59.04,24.34 ; SW1.1 3.55,16.33 ; SW1.1 4.85,15.03 ; SW1.1 3.55,13.72
  LYR4_GND w0.381: v1(32.18,54.55) 32.18,52.36 31.85,52.03 30.86,52.03 27.08,48.25 v1(27.08,46.19)
  LYR7_GND w0.375: 6,19.57 SW1.3 ; SW1.3 4.69,20.88 ; SW1.3 6,22.18 ; SW1.3 7.3,20.88 ; 39.2,73.75 MH1.1 ; MH1.1 42.5,70.45 ; MH1.1 45.81,73.75 ; MH1.1 42.5,77.06 ; 42.5,37.45 MH2.1 ; MH2.1 45.81,40.75 ; MH2.1 39.2,40.75 ; MH2.1 42.5,44.06 ; U28.3 11.01,41.58 ; U28.3 11.01,39.07 ; U28.3 12.27,40.33 ; U28.3 9.75,40.33 ; U22.1 59.75,23.38 ; U22.1 58.34,23.38 ; U22.1 59.04,24.34 ; 107.25,79.17 MH10.1 104.04,75.96 ; MH4.1 93.81,73.75 ; MH4.1 90.5,77.06 ; MH4.1 87.2,73.75 ; MH4.1 90.5,70.45 ; 3.55,13.72 SW1.1 ; SW1.1 4.85,15.03 ; SW1.1 3.55,16.33 ; 87.2,40.75 MH3.1 ; MH3.1 93.81,40.75 ; MH3.1 90.5,44.06 ; MH3.1 90.5,37.45 ; J6.4 6.04,30.28 ; J6.4 5.03,31.29 ; J6.4 5.03,29.28 ; 71.94,75.96 MH6.1 ; MH6.1 68.74,79.17 ; MH6.1 71.94,82.37 ; MH6.1 75.15,79.17 ; J10.8 55.14,18.06 ; J10.8 54.08,19.13 ; J10.8 53.01,18.06 ; J10.8 54.08,16.99 ; 110.32,41.24 J9.2 111.03,41.94 ; 12.15,80.54 J12.1 ; J12.1 12.15,82.05 ; J12.1 12.9,81.3 ; 97.16,57.48 MH7.1 ; MH7.1 97.16,63.89 ; MH7.1 93.96,60.69 ; MH7.1 100.37,60.69 ; SW1.4 7.3,13.68 ; SW1.4 6,14.98 ; SW1.4 4.69,13.68
  BOTTOM w0.121: R161.1 115.28,15.14 v1(115.29,15.12) ; v1(116.11,64.53) 116.64,63.99 R73.2 ; v2(70.18,39.43) 70.16,39.46 70.16,39.61 70.14,39.63 U1.7
  BOTTOM w0.203: v1(22.74,76.9) 23.37,76.9 23.57,77.1 J61.13 23.57,78.09 23.19,78.47 v1(22.76,78.47) ; 57.38,25.39 57.24,25.52 J14.29 ; J14.27 58.04,26 58.25,25.79 v1(58.37,25.79) ; U14.4 v1(37.46,23.1)
  BOTTOM w0.254: v1(12.25,63.51) 12.32,63.44 J62.27 ; 12.6,52.46 12.63,52.44 J62.71 14.48,52.44 14.76,52.72 14.84,52.72 ; J62.21 12.5,64.94 v1(12.27,64.71) ; R17.1 56.91,37.91 v1(57,37.82) 56.9,37.72 R19.2 56.9,36.84 56.95,36.79 ; TP9.1 97.44,53.07 v1(97.06,53.45) ; v1(38.76,25.72) 38.26,26.22 C98.2 ; v1(78.64,36.26) 78.64,36.56 R12.2 78.1,37.11 R10.1 ; 12.3,67.96 v1(12.28,67.94) J62.9 ; J62.15 12.63,66.44 v1(12.3,66.1) ; 12.17,61.94 v1(12.17,61.94) 12.17,61.94 J62.33 ; 12.35,69.33 12.46,69.44 J62.3 ; v1(52.17,25.59) 52.13,25.64 51.84,25.64 51.64,25.84 J14.43 ; 43.36,34.84 43.33,34.86 43.08,34.86 42.9,35.04 C114.1 ; 12.78,51.37 12.84,51.44 J62.75 14.74,51.44 v1(14.76,51.42) ; 7.47,54.7 7.78,55.01 U34.8 ; 14.99,51.93 14.98,51.94 J62.73 12.64,51.94 12.55,52.03 ; C61.2 83.86,73.74 v1(84.13,74) 84.52,73.61 R56.1 R55.1 85.28,73.61 v1(85.58,73.9) 85.87,73.61 R54.1 ; 12.1,58.94 v1(12.14,58.89) 12.19,58.94 J62.45 ; 67.68,79.43 71.68,79.43 MH6.1 ; J62.39 12.17,60.44 v1(12.14,60.41) 12.12,60.44 ; R174.2 v1(29.69,73.99) ; v1(11.86,70.32) 12.25,69.94 J62.1 ; J14.26 58.44,36.39 58.04,36.79 ; v1(10.16,67.93) 10.17,67.94 ; J62.57 12.47,55.94 v1(12.47,56.76) ; J62.51 12.12,57.44 v1(12.12,57.44) 12.11,57.44 ; 60.12,81.01 C107.2
  BOTTOM w0.305: J15.27 v1(90.15,25.79) ; J14.4 70.44,36.41 70.14,36.71 v1(69.9,36.71) ; D19.1 113.41,62.7 113.87,63.16 ; J15.9 v1(100.55,28.37) ; C122.2 4.77,47.48 D30.1 4.77,48.29 5.21,48.73 v1(6.94,48.73) ; D14.1 113.47,60.5 113.92,60.95 ; U20.8 U20.3 9.88,61.04 v1(9.88,61.05) ; v1(45.8,37.96) 46.02,38.18 C40.2 ; v1(107.37,37.58) 108.69,36.26 R108.2 108.69,35.18 C111.2 ; J24.19 6.82,53.54 7.06,53.78 ; U32.8 U32.3 9.92,58.06 v1(10.06,57.92) ; v1(37.44,36.26) 37.5,36.31 R573.2 ; 8.69,56.55 8.67,56.54 J24.13 ; U34.8 U34.3 10.93,55.01 v1(11.03,55.1) ; v1(60.38,25.87) 60.44,25.93 J14.21 ; U30.8 U30.3 22.49,40.99 v1(22.51,41.01) ; C28.2 47.13,40.1 v1(47.02,39.99) ; v1(113.82,61.51) 113.8,61.52 D18.1 ; U29.8 U29.3 16.53,40.82 v1(16.54,40.83) ; J24.4 2.45,61.04 v1(2.44,61.05) ; C70.1 99.32,68.24 99.34,68.26 ; D15.1 113.34,58.54 v1(113.34,58.53) ; v1(100.18,68.52) 100.13,68.46 R58.2 ; OSC1.2 v1(22.03,45.48) v1(24.31,45.48) 24.89,46.06 C168.2 ; U9.3 v1(105.39,47.84) ; C106.2 v1(15.67,20.28) ; v1(18.44,73.62) 18.34,73.51 C108.2 ; U18.3 v1(15.7,74.04) ; J15.35 v1(86.95,25.82) ; J15.15 v1(98.15,28.41) ; U24.2 85.94,24.94 C137.2 85.67,25.31 v1(86.15,25.78) J15.37 ; J15.29 v1(89.35,25.75)
  BOTTOM w0.375: U24.7 92.85,23.95 ; U24.7 92.29,25 ; U24.7 92.29,22.89 ; U24.7 91.74,23.95 ; U33.5 30.14,33.4 ; U33.5 30.14,32.29 ; U33.5 29.11,32.84 ; U33.5 31.17,32.84 ; 74.97,25.31 C140.2 74.58,25.72 ; U27.8 72.13,23.95 ; U27.8 71.58,25.01 ; U27.8 71.03,23.95 ; U27.8 71.58,22.9 ; U6.1 81.62,74.91 ; U6.1 80.67,75.77 ; U6.1 79.72,74.91 ; C151.2 18.5,40.85 ; C151.2 19,40.34 ; C151.2 17.99,40.34 ; U17.1 67.52,81.94 ; U17.1 66.49,81.38 ; U17.1 67.52,80.83 ; U17.1 68.55,81.38 ; J61.10 26.11,83.1 ; J61.10 26.11,80.19 ; J61.10 26.74,81.64 ; J61.10 25.49,81.64 ; J61.8 27.38,83.1 ; J61.8 26.76,81.64 ; J61.8 27.38,80.19 ; 34.11,17.46 C160.2 34.52,17.86 ; 66.49,80.11 U17.2 ; U17.2 67.52,80.67 ; U17.2 67.52,79.56 ; U17.2 68.55,80.11 ; 100.02,71.35 C62.2 ; C62.2 100.85,71.35 ; C62.2 100.43,70.96 ; C73.2 87.07,75.42 ; C73.2 86.06,75.42 ; C73.2 86.57,75.92 ; TP7.1 110.19,31.08 ; TP7.1 110.19,29.67 ; TP7.1 110.9,30.37 ; TP7.1 109.49,30.37 ; J24.SH1 5.83,51.54 ; J24.SH1 5.83,50.43 ; J24.SH1 4.83,50.99 ; J24.SH1 6.84,50.99 ; U17.3 68.55,78.84 ; U17.3 66.49,78.84 ; U17.3 67.52,79.4 ; U17.3 67.52,78.29 ; 34.68,81.64 J19.10 ; J19.10 35.93,81.64 ; J19.10 35.31,83.1 ; 80.78,23.95 U26.7 ; U26.7 81.89,23.95 ; U26.7 81.33,22.9 ; U26.7 81.33,25.01 ; J15.53 77.3,29.57 ; J15.53 78.7,27.72 ; J15.53 77.3,25.86 ; 58.34,23.38 U22.1 ; U22.1 59.75,23.38 ; U22.1 59.04,24.34 ; J19.8 36.58,83.1 ; J19.8 37.2,81.64 ; J19.8 35.95,81.64 ; 110.32,41.24 J9.2 111.03,41.94 ; MH1.1 42.5,76.81 ; MH1.1 42.5,70.7 ; MH1.1 39.45,73.75 ; MH1.1 45.56,73.75 ; 21.99,72.3 Q3.2 ; Q3.2 21.99,73.82 ; Q3.2 21.16,73.06 ; Q3.2 22.81,73.06 ; 69.76,23.95 U27.7 ; U27.7 70.31,22.9 ; U27.7 70.86,23.95 ; 28.01,77.74 J61.7 27.38,79.2 ; 35.79,26.22 R97.2 36.18,25.81 ; D8.1 109.44,30.42 ; D8.1 107.53,30.42 ; D8.1 108.49,29.46 ; D8.1 108.49,31.37 ; 84.95,36.57 J15.40 84.95,34.06 ; 97.16,57.48 MH7.1 ; MH7.1 97.16,63.89 ; MH7.1 100.37,60.69 ; MH7.1 93.96,60.69 ; C500.2 29.13,36.15 ; C500.2 28.72,35.76 ; C500.2 28.3,36.15 ; 93.75,34.06 J15.18 ; J15.18 94.28,35.32 ; J15.18 93.75,36.57 ; J10.8 55.14,18.06 ; J10.8 53.01,18.06 ; J10.8 54.08,19.13 ; J10.8 54.08,16.99 ; 4.69,20.88 SW1.3 ; SW1.3 6,22.18 ; SW1.3 7.3,20.88 ; SW1.3 6,19.57 ; SW1.4 7.3,13.68 ; SW1.4 6,14.98 ; SW1.4 4.69,13.68 ; C150.2 15.09,40.34 ; C150.2 14.08,40.34 ; C150.2 14.58,40.85 ; C15.2 67.71,40.17 ; C15.2 67.3,39.78 ; C15.2 68.12,39.78 ; 80.95,34.06 J15.50 80.95,36.57 ; 8.51,16.77 D12.1 9.02,16.27 ; J24.SH3 3.63,64.14 ; J24.SH3 3.63,63.03 ; J24.SH3 4.64,63.59 ; J24.SH3 2.63,63.59 ; 75.54,23.95 U26.2 74.98,25.01 ; 8.83,30.39 C37.2 ; C37.2 9.22,29.98 ; C37.2 9.22,30.8 ; 9.05,30.81 R35.2 ; R35.2 9.05,31.82 ; R35.2 8.55,31.32 ; J62.77 15.56,50.29 ; J62.77 12.97,50.29 ; J62.77 14.27,49.48 ; 93.56,22.89 U24.8 ; U24.8 94.12,23.95 ; U24.8 93.01,23.95 ; U24.8 93.56,25 ; 100.97,68.09 C66.2 101.38,67.7 ; 86.5,23.95 U24.2 85.39,23.95 ; 48.84,36.57 J14.50 48.84,34.06 ; C153.2 24.59,40.87 ; C153.2 24.09,40.37 ; C153.2 25.1,40.37 ; 87.35,34.06 J15.34 87.35,36.57 ; J19.12 34.04,83.1 ; J19.12 33.41,81.64 ; J19.12 34.66,81.64 ; 52.84,36.57 J14.40 52.84,34.06 ; OSC1.2 22.06,46.37 ; OSC1.2 21.14,45.58 ; OSC1.2 21.14,47.16 ; OSC1.2 20.23,46.37 ; 66.49,77.57 U17.4 ; U17.4 67.52,78.13 ; U17.4 68.55,77.57 ; U17.4 67.52,77.02 ; 68.74,79.17 MH6.1 ; MH6.1 71.94,82.37 ; MH6.1 75.15,79.17 ; MH6.1 71.94,75.96 ; 54.29,73.81 TP17.1 ; TP17.1 54.99,73.11 ; TP17.1 54.99,74.52 ; 39.45,40.75 MH2.1 ; MH2.1 42.5,43.81 ; MH2.1 42.5,37.7 ; MH2.1 45.56,40.75 ; J6.4 5.03,31.29 ; J6.4 6.04,30.28 ; J6.4 5.03,29.28 ; U28.3 11.01,41.58 ; U28.3 11.01,39.07 ; U28.3 12.27,40.33 ; 28.03,77.74 J61.5 29.28,77.74 ; 2.86,44.55 C504.2 2.46,44.96 ; 56.7,73.83 C34.1 56.2,74.33 ; 23.25,72.74 R40.2 22.84,73.14 ; 31.82,81.64 J61.2 31.19,83.1 ; J19.2 40.39,83.1 ; J19.2 39.76,81.64 ; J19.2 41.01,81.64 ; 3.55,13.72 SW1.1 ; SW1.1 4.85,15.03 ; SW1.1 3.55,16.33 ; 15.56,71.09 J62.76 12.97,71.09 ; 82.6,22.9 U26.8 ; U26.8 82.6,25.01 ; U26.8 82.05,23.95 ; U26.8 83.16,23.95 ; MH4.1 93.56,73.75 ; MH4.1 90.5,76.81 ; MH4.1 87.45,73.75 ; C152.2 20.25,40.92 ; C152.2 19.74,40.42 ; C152.2 20.75,40.42 ; C65.2 100.31,69.86 ; C65.2 99.91,69.45 ; C65.2 100.31,69.04 ; J15.54 106.6,29.57 ; J15.54 108,27.72 ; J15.54 105.19,27.72 ; J15.54 106.6,25.86 ; 98.45,68.48 C69.1 97.95,67.97 ; 37.22,81.64 J19.6 ; J19.6 37.85,83.1 ; J19.6 38.47,81.64 ; 4.83,63.59 J24.SH4 ; J24.SH4 5.83,64.14 ; J24.SH4 6.84,63.59 ; 68.44,25.86 J14.9 68.44,28.37 ; 10.36,15.02 J13.8 13.27,15.02 ; 107.25,79.17 MH10.1 104.04,75.96 ; 54.84,25.86 J14.35 54.84,28.37 ; 73.09,27.72 J14.54 ; J14.54 74.49,29.57 ; J14.54 74.49,25.86 ; 63.41,23.95 U27.2 ; U27.2 64.51,23.95 ; U27.2 63.96,25.01 ; U27.2 63.96,22.9 ; 14.87,75.65 TP13.1 ; TP13.1 15.57,76.35 ; TP13.1 16.28,75.65 ; TP13.1 15.57,74.95 ; 75.46,73.73 C60.2 75.88,74.12 ; 63.35,24.92 C142.2 63.75,25.34 ; 2.63,58.04 J24.10 4.64,58.04 ; 56.73,73.83 C33.1 57.23,74.33 ; 78.49,37.1 R12.2 78.1,36.69 ; J14.15 66.04,28.37 ; J14.15 65.51,27.12 ; J14.15 66.04,25.86 ; 97.62,27.12 J15.15 98.15,25.86 ; J61.12 24.84,83.1 ; J61.12 24.22,81.64 ; J61.12 25.47,81.64 ; 76.6,75.52 C68.2 76.21,75.11 ; 55.24,36.57 J14.34 55.24,34.06 ; MH3.1 93.56,40.75 ; MH3.1 90.5,43.81 ; MH3.1 90.5,37.7 ; MH3.1 87.45,40.75 ; R651.1 28.72,35.02 ; R651.1 28.3,34.63 ; R651.1 29.13,34.63 ; 41.23,44.37 TP6.1 ; TP6.1 41.23,45.78 ; TP6.1 41.93,45.08 ; 14.53,74.04 U18.3 15.13,74.45 ; 43.79,27.72 J14.53 46.6,27.72 ; 92.55,28.37 J15.21 92.55,25.86 ; 90.55,34.06 J15.26 90.55,36.57 ; 97.82,70.67 C71.1 97.31,71.17 ; 83.75,25.86 J15.43 83.75,28.37 ; 63.91,47.02 C16.2 64.92,47.02 ; 36.94,72.86 R173.2 ; R173.2 36.94,73.87 ; R173.2 37.45,73.37 ; 54.04,25.86 J14.37 54.04,28.37 ; 4.64,50.99 J24.SH2 3.63,50.43 ; 98.66,70.99 C72.1 99.07,71.38 ; 38.49,81.64 J19.4 ; J19.4 39.74,81.64 ; J19.4 39.12,83.1 ; J12.1 12.9,81.3 ; J12.1 12.15,82.05 ; J12.1 12.15,80.54 ; 2.63,55.04 J24.16 4.64,55.04
  BOTTOM w0.381: J61.5 28.65,78.93 v1(28.32,79.26) ; J61.3 29.92,78.8 29.62,79.11 v1(29.62,79.23) ; J14.18 61.64,36.48 v2(61.83,36.66) ; J24.19 4.9,53.54 4.75,53.68 ; v1(7.6,59.52) 7.58,59.54 J24.7 ; U9.3 U9.8 105.39,50.1 ; 55.24,34.06 55.24,32.98 54.71,32.45 ; v1(58.93,74.64) 58.88,74.59 C35.1 ; v1(108.84,48.3) 108.82,48.32 U8.3 U8.8 108.82,50.58 ; v1(66.6,37.35) 66.7,37.45 R14.2 ; 4.47,62.9 4.84,62.54 J24.1 7.08,62.54 7.09,62.55 ; v1(47.27,35.93) 47.43,36.09 47.3,36.22 47.3,36.93 R21.2 ; J61.1 31.19,79.01 31.75,79.57 v1(31.75,79.79)
  BOTTOM w0.508: C29.2 v1(42.78,47.85) ; C16.2 v1(64.41,46.45)
  vias: v1(2.11,55.03) v1(2.16,64.3) v1(2.14,59.02) v1(2.14,57.21) v1(2.14,45.27) v1(2.16,44.06) v1(2.39,54.06) v1(2.97,43.22) v1(3.08,67.02) v1(3.38,62.8) v1(3.36,50.1) v1(3.81,64.65) v1(3.74,48.96) v1(4.37,40.86) v1(4.5,37.81) v1(4.55,68.54) v1(4.7,28.84) v1(4.63,26.53) v1(4.85,16.34) v1(5.03,18.93) v1(5.59,67.4) v1(5.92,31.58) v1(5.97,29.32) v1(6.02,70.6) v1(6.61,19.57) v1(6.63,15.05) v1(6.94,50.94) v1(7.85,62.7) v1(7.9,49.8) v1(7.93,12.74) v1(8.21,67.42) v1(8.23,64.02) v1(8.79,51.19) v1(8.87,49.16) v1(8.99,30.82) v1(8.99,29.98) v1(9.04,72.15) v1(9.32,70.6) v1(9.38,63.99) v1(9.78,50.56) v1(9.93,63.28) v1(9.96,59.52) v1(10.24,56.5) v1(10.26,43.88) v1(10.44,7.3) v1(10.49,5.57) v1(10.57,34.17) v1(10.7,75.25) v1(10.7,74.41) v1(10.67,33.16) v1(10.85,31.89) v1(10.98,2.7) v1(11.13,82.84) v1(11.38,62.55) v1(11.36,61.1) v1(11.41,56.37) v1(11.46,59.5) v1(11.56,58.1) v1(11.76,50.38) v1(11.79,48.81) v1(12.09,72.07) v1(12.04,44.82) v1(12.17,51.45) v1(12.4,2.22) v1(12.42,1.36) v1(12.6,71.18) v1(12.55,41.39) v1(12.85,75.12) v1(13.01,50.41) v1(13.31,26.63) v1(13.44,43.83) v1(13.54,6.59) v1(13.77,79.44) v1(13.79,2.22) v1(13.82,1.36) v1(14.1,45.3) v1(14.07,5.42) v1(14.15,83.04) v1(14.15,6.29) v1(14.18,4.96) v1(14.58,75.63) v1(15.19,2.22) v1(15.22,1.36) v1(15.24,20.28) v1(15.78,8.62) v1(15.98,9.97) v1(16.16,7.25) v1(16.23,60.29) v1(16.26,59.09) v1(16.33,80.23) v1(16.39,63.74) v1(16.36,61.76) v1(16.38,57.21) v1(16.33,46.75) v1(16.41,26.53) v1(16.46,56.12) v1(16.69,2.22) v1(16.72,1.36) v1(17.2,83.07) v1(17.22,66.23) v1(17.83,2.22) v1(17.86,1.36) v1(18.16,63.72) v1(18.42,67.37) v1(18.37,61.78) v1(18.54,40.83) v1(18.62,42.25) v1(18.75,2.5) v1(19.15,6.16) v1(19.51,5.09) v1(19.46,3.01) v1(19.71,26.43) v1(19.79,11.72) v1(19.84,63.77) v1(19.97,61.78) v1(20.07,45.58) v1(20.2,40.83) v1(20.63,42.58) v1(20.86,76.59) v1(21.44,11.92) v1(22.1,83.12) v1(22.28,67.88) v1(22.33,69.23) v1(22.46,71.97) v1(22.51,26.73) v1(22.53,80.43) v1(23.32,11.77) v1(23.85,69.15) v1(23.93,10.5) v1(24.59,49.26) v1(24.59,40.91) v1(24.69,7.84) v1(24.84,83.17) v1(24.84,50.46) v1(24.92,68.44) v1(25.02,46.47) v1(25.33,11.44) v1(25.58,27.06) v1(25.73,63) v1(25.96,79.82) v1(26.19,83.17) v1(26.52,60.51) v1(26.52,26.53) v1(26.88,63.64) v1(26.88,58.89) v1(26.88,25.28) v1(27.13,7.07) v1(27.31,80) v1(27.41,83.12) v1(27.41,79.23) v1(27.59,35.57) v1(27.59,33.62) v1(27.56,31.58) v1(27.54,29.93) v1(28.68,60.46) v1(28.81,58.91) v1(28.96,35.11) v1(29.43,70.61) v1(29.49,69.71) v1(29.67,7.07) v1(30.05,74.28) v1(30.41,69.71) v1(30.36,66.03) v1(30.56,62.9) v1(30.84,58.94) v1(31.19,83.15) v1(31.3,32.83) v1(31.6,37.02) v1(31.6,35.01) v1(31.93,62.83) v1(32.16,66.2) v1(32.21,7.07) v1(32.31,83.12) v1(32.69,46.6) v1(32.72,46.14) v1(33.2,47.03) v1(33.2,46.6) v1(33.17,46.14) v1(33.4,83.12) v1(33.35,62.72) v1(33.51,47.87) v1(33.63,47.03) v1(33.63,46.6) v1(33.86,18.78) v1(34.06,47.03) v1(34.7,83.12) v1(34.75,7.07) v1(35.61,71.03) v1(35.61,24.68) v1(35.89,70.67) v1(35.84,23.18) v1(35.99,83.12) v1(36.3,53.96) v1(37.16,83.12) v1(37.24,65.26) v1(37.47,53.96) v1(37.44,39.03) v1(37.47,12.51) v1(37.95,40.75) v1(38.43,83.12) v1(38.48,23.79) v1(38.69,13.93) v1(38.79,65.42) v1(38.86,72.55) v1(38.99,49.39) v1(39.3,38.67) v1(39.65,83.12) v1(39.68,37.3) v1(39.88,50.76) v1(40.36,30.44) v1(40.67,83.17) v1(41.25,46.29) v1(41.63,30.16) v1(41.86,46.98) v1(41.89,34.51) v1(41.96,77.66) v1(42.4,79.74) v1(42.4,29.55) v1(42.95,28.69) v1(43.79,29.15) v1(44.38,80.3) v1(44.53,46.7) v1(44.53,45.94) v1(44.53,45.15) v1(44.94,78.62) v1(45.49,77.38) v1(45.87,3.29) v1(46.23,80.17) v1(46.36,73.19) v1(46.43,7.76) v1(46.54,11.49) v1(46.69,20.79) v1(46.71,19.87) v1(46.79,23.51) v1(47.22,77.43) v1(47.58,65.24) v1(48.01,80.38) v1(47.96,79.08) v1(48.14,82) v1(48.41,32.27) v1(48.39,31.2) v1(48.36,30.26) v1(48.41,7.48) v1(48.52,75.17) v1(48.54,34) v1(48.64,13.58) v1(48.8,40.09) v1(48.9,83.1) v1(48.85,11.21) v1(49.3,30.24) v1(49.35,32.24) v1(49.33,31.18) v1(49.48,33.97) v1(49.86,77.48) v1(50.4,81.93) v1(50.35,79.34) v1(50.5,4.08) v1(50.6,39.97) v1(50.56,31.16) v1(50.54,30.22) v1(50.55,28.76) v1(50.72,33.96) v1(50.7,20.46) v1(50.78,22.01) v1(50.98,52.95) v1(51.39,39.48) v1(51.44,83.1) v1(51.72,58.38) v1(51.74,59.04) v1(51.89,32.24) v1(51.87,31.18) v1(51.84,30.24) v1(51.82,3.14) v1(51.95,81.7) v1(51.97,54.16) v1(52,7.94) v1(52.02,33.97) v1(52.12,51.4) v1(52.17,38.8) v1(52.3,20.46) v1(52.3,11.06) v1(52.4,28.51) v1(52.71,66.51) v1(52.76,65.26) v1(52.81,31.15) v1(52.78,30.21) v1(52.83,32.22) v1(52.96,33.95) v1(53.04,81.8) v1(53.19,37.86) v1(53.29,51.45) v1(53.24,39.38) v1(53.24,13.12) v1(53.65,6.74) v1(53.98,83.1) v1(54.1,59.02) v1(54.1,58.41) v1(54.05,29.65) v1(54.08,20.79) v1(54.28,28.54) v1(54.26,16.27) v1(54.23,15.51) v1(55.55,65.26) v1(55.73,37.93) v1(56.16,74.54) v1(56.14,25.62) v1(56.14,25.16) v1(57.08,45.17) v1(57.03,44.18) v1(57.05,43.42) v1(57.25,74.64) v1(57.38,36.77) v1(57.41,31.89) v1(57.53,59.04) v1(57.53,58.43) v1(57.97,23.63) v1(58.09,57.26) v1(58.09,56.65) v1(58.24,51.35) v1(58.24,44.13) v1(58.3,24.04) v1(58.4,4.38) v1(58.93,4.38) v1(59.29,83.1) v1(59.41,37.05) v1(59.41,30.64) v1(59.46,55.69) v1(59.44,51.37) v1(59.44,44.11) v1(60.05,81.47) v1(60.02,24.04) v1(60.15,74.97) v1(60.63,44.31) v1(61.04,56.17) v1(61.14,23.46) v1(61.37,6.49) v1(61.67,82.97) v1(61.8,2.3) v1(61.83,7) v1(61.83,2.93) v1(62.97,43.57) v1(63.5,58.15) v1(63.5,44.44) v1(63.53,57.64) v1(63.6,45.58) v1(63.88,25.59) v1(63.88,25.11) v1(63.96,22.41) v1(63.96,21.93) v1(64.04,40.78) v1(64.42,37.38) v1(64.37,25.59) v1(64.37,25.11) v1(64.47,82.97) v1(64.47,35.29) v1(64.44,22.41) v1(64.44,21.93) v1(64.54,45.43) v1(64.75,43.62) v1(64.85,40.75) v1(64.87,31.84) v1(64.9,31.1) v1(65.33,81.5) v1(65.43,27.06) v1(66.09,31.05) v1(66.19,31.81) v1(66.5,73.62) v1(67.21,82.99) v1(67.29,81.52) v1(68.15,63.33) v1(68.56,80.63) v1(68.56,77.96) v1(68.76,25.67) v1(69.62,82.99) v1(70.34,63.33) v1(71.94,37.15) v1(72.37,60.31) v1(72.47,29.27) v1(72.6,63.36) v1(72.6,18.58) v1(72.6,18.1) v1(72.75,37.15) v1(72.72,34.63) v1(72.9,83.07) v1(72.95,37.86) v1(73.08,18.58) v1(73.08,18.1) v1(73.38,60.41) v1(73.41,30.26) v1(73.51,58.38) v1(73.43,31.97) v1(73.61,37.91) v1(73.76,35.42) v1(73.92,43.01) v1(74.55,36.23) v1(75.34,74.94) v1(75.8,79.16) v1(75.85,76.75) v1(75.97,81.19) v1(76.2,82.64) v1(76.2,43.29) v1(76.2,42.3) v1(76.3,61.78) v1(76.23,33.24) v1(76.33,25.92) v1(76.33,25.18) v1(77.04,58.18) v1(77.19,17.11) v1(77.29,76.19) v1(77.35,57.14) v1(77.5,59.02) v1(77.45,55.87) v1(77.68,17.11) v1(77.93,60.21) v1(78.23,61.78) v1(78.34,17.11) v1(78.56,45.94) v1(78.62,43.7) v1(78.56,35.47) v1(78.69,80.25) v1(78.67,41.19) v1(78.82,17.11) v1(79.28,83.02) v1(79.83,77.53) v1(79.89,61.71) v1(80.09,19.9) v1(80.09,19.42) v1(80.32,46.04) v1(80.24,41.21) v1(80.42,70.37) v1(80.47,43.24) v1(80.57,19.9) v1(80.57,19.42) v1(81.33,44) v1(81.79,45.07) v1(81.89,70.37) v1(82.02,74.92) v1(82.1,33.82) v1(82.22,61.71) v1(82.32,36.74) v1(82.58,46.29) v1(82.55,33.82) v1(82.63,79.36) v1(82.76,36.74) v1(82.83,31.25) v1(82.86,30.7) v1(82.86,30.26) v1(82.88,29.7) v1(82.88,29.22) v1(83.11,75.96) v1(83.31,31.25) v1(83.34,30.7) v1(83.34,30.26) v1(83.37,29.7) v1(83.37,29.22) v1(83.72,28.38) v1(84.2,81.22) v1(84.48,83.12) v1(84.91,33.84) v1(85.37,61.68) v1(85.47,66.51) v1(86.62,81.24) v1(86.97,66.38) v1(87.2,75.42) v1(87.4,33.9) v1(88.12,61.68) v1(88.5,83.12) v1(89.46,77.79) v1(89.84,61.4) v1(90.02,81.32) v1(90.48,36.69) v1(91.21,78.68) v1(91.95,64.63) v1(92.31,22.87) v1(92.59,28.38) v1(93.45,63.11) v1(93.58,22.87) v1(93.75,34.02) v1(94.41,64.71) v1(94.9,51.19) v1(95.3,50.81) v1(95.61,55.94) v1(95.61,50.38) v1(96.75,69.38) v1(96.78,55.94) v1(97.13,70.67) v1(97.34,67.75) v1(98.53,70.75) v1(98.63,69.07) v1(98.76,56.04) v1(99.09,50.05) v1(99.42,48.22) v1(99.7,70.12) v1(100.61,49.14) v1(100.82,50.23) v1(100.84,31.61) v1(100.84,31.13) v1(101.2,60.18) v1(101.32,31.61) v1(101.32,31.13) v1(101.83,31.66) v1(101.83,31.18) v1(102.06,50.2) v1(102.24,43.83) v1(102.31,31.66) v1(102.31,31.18) v1(102.47,68.77) v1(102.62,55.28) v1(102.87,66.79) v1(102.97,69.33) v1(103.23,64.71) v1(103.63,63.38) v1(103.71,47.69) v1(103.81,50.56) v1(103.76,43.78) v1(104.63,29.32) v1(104.63,28.84) v1(105.11,29.32) v1(105.11,28.84) v1(105.31,50.99) v1(105.74,74.51) v1(106.07,75.7) v1(106.61,74.18) v1(106.68,71.18) v1(106.78,72.63) v1(106.83,50.99) v1(107.04,76.26) v1(107.29,70.5) v1(107.75,79.87) v1(107.72,77.61) v1(108.56,29.37) v1(108.56,28.89) v1(108.71,51.55) v1(108.79,71.08) v1(109.04,29.37) v1(109.04,28.89) v1(109.25,80.73) v1(109.27,78.83) v1(109.3,77) v1(109.76,41.24) v1(109.91,52.08) v1(110.34,51.35) v1(110.57,49.8) v1(110.72,48.02) v1(110.9,58.51) v1(111.15,71.87) v1(111.15,71.39) v1(111.25,48.65) v1(111.41,50.1) v1(111.48,52.08) v1(111.48,14.92) v1(111.56,51.07) v1(111.61,42.46) v1(111.61,41.46) v1(111.64,47.69) v1(112.4,51.5) v1(112.4,50.3) v1(112.4,14.9) v1(112.42,49.21) v1(112.45,48.22) v1(112.42,47.59) v1(112.45,13.93) v1(112.8,42.4) v1(112.8,41.41) v1(113.44,14.87) v1(113.46,13.55) v1(113.95,51.42) v1(113.95,50.23) v1(113.97,49.14) v1(114,48.14) v1(114,42.38) v1(114,41.39) v1(114.23,16.17) v1(114.25,14.85) v1(114.28,13.52) v1(114.48,70.8) v1(114.48,70.37) v1(114.51,62.83) v1(114.45,43.4) v1(114.61,57.75) v1(114.81,58.94) v1(115.12,70.83) v1(115.12,70.37) v1(115.04,66.94) v1(115.04,66.51) v1(115.06,51.37) v1(115.34,49.14) v1(115.45,43.4) v1(115.5,17.23) v1(115.67,70.78) v1(115.67,70.34) v1(115.75,60.49) v1(115.78,58.2) v1(115.83,66.94) v1(115.83,66.51) v1(116.46,66.15) v1(116.54,64.65) v1(116.66,59.45) v1(116.89,66.15) v1(116.97,64.65) v1(116.99,63.21) v1(116.92,58.46) v2(59.59,31.97) v2(61.11,32.45)
GND_EARTH: length 896.2
  TOP w0.121: J25.S1 9.45,0.6 9.27,0.42 v1(8.59,0.42)
  TOP w0.381: v1(22.41,0.39) 21.44,0.39 20.96,0.88 20.47,0.39 v1(19.87,0.39)
  TOP w0.425: J3.2 96.19,81.19 ; J3.2 94.63,82.75 ; J3.2 94.63,79.64 ; 114.8,1.93 MH13.1 ; MH13.1 114.8,10.67 ; MH13.1 119.17,6.3 ; J18.13 38.22,8.47 ; J18.13 38.22,5.96 ; J18.13 39.47,7.21 ; 4.8,1.93 MH12.1 0.43,6.3 ; 114.8,80.67 MH14.1 119.17,76.3 ; 98.58,81.19 J3.1 100.13,82.75 ; 4.8,71.93 MH11.1 0.43,76.3 ; 94.63,77.75 J3.3 96.19,76.19
  TOP w0.635: 63.11,0.63 63.1,0.62 ; 97.77,76.29 97.86,76.19 J3.4 99.62,76.71 99.62,78.65
  TOP w0.889: J10.14 57.61,12.11 57.61,10.6 ; J10.13 40.29,10.75 40.29,10.22
  TOP w1.27: J9.21 102.66,39.2 105.77,39.2 ; J9.22 117.74,45.69 117.78,45.73 ; 113.71,39.19 J9.20 111.46,39.38 107.29,39.38 ; J8.S4 111.06,54.6 113.39,54.6 ; 22.04,7.19 22.04,6.78 21.16,5.9 21.16,1.08 20.96,0.88
  LYR2_GND w0.425: J3.2 96.19,81.19 ; J3.2 94.63,79.64 ; J3.2 94.63,82.75 ; MH13.1 119.17,6.3 ; MH13.1 114.8,1.93 ; MH13.1 114.8,10.67 ; 94.63,77.75 J3.3 96.19,76.19 ; 4.8,1.93 MH12.1 0.43,6.3 ; 100.13,82.75 J3.1 98.58,81.19 ; J18.13 39.47,7.21 ; J18.13 38.22,5.96 ; J18.13 38.22,8.47 ; 114.8,80.67 MH14.1 119.17,76.3
  LYR2_GND w1.27: J9.21 J9.20 114.85,39.19 114.99,39.33 ; J3.4 100.02,76.19 98.28,77.94 ; 117.78,45.71 117.77,45.69 J9.22
  LYR3 w0.425: 94.63,79.64 J3.2 ; J3.2 96.19,81.19 ; J3.2 94.63,82.75 ; MH13.1 119.17,6.3 ; MH13.1 114.8,1.93 ; MH13.1 114.8,10.67 ; 0.43,6.3 MH12.1 4.8,1.93 ; 119.17,76.3 MH14.1 114.8,80.67 ; J18.13 38.22,8.47 ; J18.13 38.22,5.96 ; J18.13 39.47,7.21 ; 98.58,81.19 J3.1 100.13,82.75 ; 96.19,76.19 J3.3 94.63,77.75
  LYR3 w0.508: 57.79,10.6 57.79,11.94 J10.14
  LYR3 w1.27: 114.39,39.19 J9.20 J9.21 ; J18.14 21.19,6.28 21.19,3.62 ; 40.69,10.48 40.69,11.16 J10.13 ; J3.4 100.13,76.31 98.3,78.14 ; J9.22 117.87,45.69 117.91,45.73
  LYR4_GND w0.425: 38.22,5.96 J18.13 ; J18.13 39.47,7.21 ; J18.13 38.22,8.47 ; 119.17,76.3 MH14.1 114.8,80.67 ; 94.63,79.64 J3.2 ; J3.2 94.63,82.75 ; J3.2 96.19,81.19 ; 114.8,1.93 MH13.1 ; MH13.1 114.8,10.67 ; MH13.1 119.17,6.3 ; 4.8,71.93 MH11.1 0.43,76.3 ; 100.13,82.75 J3.1 98.58,81.19 ; 0.43,6.3 MH12.1 4.8,1.93 ; 94.63,77.75 J3.3 96.19,76.19
  LYR4_GND w0.635: 63.2,0.55 63.11,0.64 J11.S3 J11.S4 ; 57.74,10.71 57.74,11.99 J10.14 ; J11.S1 J11.S2 65.97,0.78
  LYR4_GND w1.016: 114.4,39.28 114.31,39.19 J9.20 108.85,39.19 108.82,39.23 ; J10.13 40.69,11.16 40.69,10.63 ; J9.21 105.3,39.19 105.31,39.2
  LYR4_GND w1.27: 99.11,77.51 100.13,76.49 J3.4 ; 22.04,7.19 22.04,6.71 21.31,5.98 ; 113.62,54.39 113.55,54.46 J8.S4 J8.S1 ; 114.71,45.63 114.65,45.69 J9.22
  LYR4_GND w1.524: J9.23 J9.22
  LYR5_PWR w0.425: J18.13 39.47,7.21 ; J18.13 38.22,5.96 ; J18.13 38.22,8.47 ; 94.63,77.75 J3.3 96.19,76.19 ; 4.8,71.93 MH11.1 0.43,76.3 ; 100.13,82.75 J3.1 98.58,81.19 ; 119.17,76.3 MH14.1 114.8,80.67 ; J3.2 94.63,82.75 ; J3.2 96.19,81.19 ; J3.2 94.63,79.64 ; MH13.1 114.8,10.67 ; MH13.1 119.17,6.3 ; MH13.1 114.8,1.93 ; 4.8,1.93 MH12.1 0.43,6.3
  LYR5_PWR w0.635: J10.14 57.86,11.86 57.86,10.55 ; 65.97,0.78 J11.S2 J11.S1 ; 63.15,0.57 63.11,0.61 J11.S3 J11.S4
  LYR5_PWR w1.27: 114.63,39.13 114.57,39.19 J9.20 J9.21 ; 22.04,7.19 22.04,6.66 21.24,5.85 ; 98.43,77.89 100.12,76.19 J3.4 ; J10.13 40.59,11.06 40.59,10.45 ; 114.66,45.55 114.52,45.69 J9.22 J9.23 ; J8.S1 J8.S4 113.88,54.46 114.15,54.19
  LYR6 w0.425: 98.58,81.19 J3.1 100.13,82.75 ; MH13.1 114.8,10.67 ; MH13.1 114.8,1.93 ; MH13.1 119.17,6.3 ; 0.43,76.3 MH11.1 4.8,71.93 ; 38.22,5.96 J18.13 ; J18.13 38.22,8.47 ; J18.13 39.47,7.21 ; J3.2 96.19,81.19 ; J3.2 94.63,79.64 ; J3.2 94.63,82.75 ; 114.8,80.67 MH14.1 119.17,76.3 ; 112.5,67.6 112.73,67.6 ; 0.43,6.3 MH12.1 4.8,1.93 ; 94.63,77.75 J3.3 96.19,76.19
  LYR6 w0.635: 65.97,0.78 J11.S2 J11.S1 ; 63.12,0.62 63.11,0.64 J11.S3 J11.S4 ; 57.81,10.53 57.5,10.84 J10.14 ; J10.13 40.67,11.13 40.67,10.45
  LYR6 w1.27: J3.4 100.13,76.31 98.73,77.71 ; 22.04,7.19 22.04,6.53 21.31,5.8 ; J8.S2 J8.S3 112.5,67.6 113.31,68.41 ; J9.21 J9.20 114.72,39.19 114.73,39.2
  LYR6 w2.032: J8.S1 J8.S4 113.37,54.46 113.62,54.22
  LYR7_GND w0.425: 96.19,76.19 J3.3 94.63,77.75 ; J3.2 96.19,81.19 ; J3.2 94.63,82.75 ; J3.2 94.63,79.64 ; 4.8,71.93 MH11.1 0.43,76.3 ; 0.43,6.3 MH12.1 4.8,1.93 ; 114.8,80.67 MH14.1 119.17,76.3 ; J18.13 39.47,7.21 ; J18.13 38.22,5.96 ; J18.13 38.22,8.47 ; 119.17,6.3 MH13.1 114.8,10.67 ; 98.58,81.19 J3.1 100.13,82.75
  LYR7_GND w0.635: 63.07,0.62 63.11,0.66 J11.S3 J11.S4 ; 65.97,0.78 J11.S2 J11.S1
  LYR7_GND w0.889: 57.53,10.43 57.5,10.46 J10.14
  LYR7_GND w1.27: 40.41,10.2 40.41,10.88 J10.13 ; J3.4 100.07,76.19 98.4,77.86 ; MH13.1 117.63,3.47 117.63,1.69 ; MH13.1 112.83,8.27 112.83,10.88 ; MH13.1 114.8,4.32 112.3,1.82 ; MH13.1 117.91,9.41 117.91,11.04 ; MH11.1 4.8,76.37 1.5,79.67 ; 1.12,10.12 4.8,6.44 MH12.1 ; 21.29,5.7 22.04,6.45 22.04,7.19 ; J9.21 J9.20 114.59,39.19 114.61,39.2 ; 113.97,54.37 113.88,54.46 J8.S4 J8.S1 ; 113.36,68.46 112.5,67.6 J8.S3 J8.S2
  BOTTOM w0.121: 117.99,47.11 v1(117.81,46.93) ; C505.2 117.99,41.49 v1(117.68,41.19)
  BOTTOM w0.381: v1(19.87,0.39) 20.4,0.39 20.96,0.95 21.52,0.39 v1(22.41,0.39)
  BOTTOM w0.425: 100.13,82.75 J3.1 98.58,81.19 ; 119.17,6.3 MH13.1 114.8,10.67 ; 4.8,71.93 MH11.1 0.43,76.3 ; 117.99,48.01 117.99,47.11 ; 115.23,76.3 v1(117.34,76.3) 119.17,76.3 ; 109.64,39.19 J9.20 113.66,39.19 ; 38.22,5.96 J18.13 ; J18.13 39.47,7.21 ; J18.13 38.22,8.47 ; J3.2 96.19,81.19 ; J3.2 94.63,82.75 ; J3.2 94.63,79.64 ; 112.5,67.6 112.73,67.6 ; 94.63,77.75 J3.3 96.19,76.19
  BOTTOM w0.635: J11.S1 J11.S2 65.97,0.78 ; 97.87,75.93 99.87,75.93 J3.4 99.7,76.63 99.7,78.22 ; J11.S4 J11.S3 63.11,0.64 63.12,0.62
  BOTTOM w0.889: 112.22,80.94 112.22,78.88 MH14.1 ; 57.61,10.48 57.61,12.11 J10.14 ; 2.36,2.42 4.8,4.86 MH12.1 ; MH12.1 4.8,6.57 1.55,9.82 ; MH12.1 2.55,6.3 0.74,8.11 ; MH14.1 115.23,76.3 118.54,72.99 ; MH14.1 118.24,79.74 118.24,80.66 ; MH13.1 112.07,9.03 112.07,10.48 ; MH13.1 114.8,4.82 117.48,2.15 ; MH13.1 117.83,9.33 117.83,10.5 ; MH13.1 112.68,4.18 112.68,1.74 ; MH11.1 4.8,76.65 1.53,79.92 ; 40.62,10.38 40.62,11.08 J10.13
  BOTTOM w1.27: 113.39,68.49 112.5,67.6 J8.S3 J8.S2 ; 20.96,0.95 21.16,1.15 21.16,5.93 22.04,6.81 22.04,7.19 ; J9.21 102.76,39.31 105.77,39.31 ; 113.62,54.37 111.02,54.37 J8.S4 J8.S1 ; 108.05,39.13 111.59,39.13 J9.20 111.71,39.25 115.24,39.25
  vias: v1(0.46,78.17) v1(0.46,75.63) v1(0.43,73.09) v1(0.51,70.75) v1(0.51,68.21) v1(0.51,65.67) v1(0.49,63.13) v1(0.49,60.59) v1(0.49,58.05) v1(0.46,50.81) v1(0.49,48.73) v1(0.49,46.19) v1(0.49,43.65) v1(0.51,19.93) v1(0.51,17.39) v1(0.51,14.85) v1(0.49,11.65) v1(0.49,9.11) v1(0.49,6.57) v1(0.49,4.03) v1(0.54,55.87) v1(0.59,53.33) v1(1.45,40.63) v1(1.5,27.65) v1(1.5,25.11) v1(1.5,22.57) v1(1.48,21.22) v1(1.68,37.6) v1(2.41,75.43) v1(2.41,5.43) v1(2.6,77.57) v1(2.6,7.57) v1(2.87,31.63) v1(2.95,34.4) v1(3,24.78) v1(3.03,27.47) v1(3.08,26.15) v1(3.05,23.46) v1(3.23,29.4) v1(3.74,0.75) v1(3.93,73.91) v1(3.93,3.91) v1(4.36,78.8) v1(4.36,8.8) v1(6.07,74.1) v1(6.07,4.1) v1(6.43,78.25) v1(6.43,8.25) v1(6.68,0.39) v1(7.34,76.3) v1(7.34,6.3) v1(8.77,22.67) v1(9.2,22.67) v1(9.63,22.67) v1(10.06,22.64) v1(11.76,0.39) v1(14.79,0.39) v1(17.33,0.39) v1(25.2,0.39) v1(27.74,0.39) v1(30.28,0.39) v1(32.82,0.39) v1(35.49,0.39) v1(38.08,0.47) v1(40.62,0.47) v1(43.16,0.47) v1(45.7,0.47) v1(48.49,0.47) v1(51.03,0.47) v1(53.57,0.47) v1(56.11,0.47) v1(58.78,0.47) v1(61.32,0.47) v1(63.86,0.47) v1(66.4,0.47) v1(69.19,0.47) v1(71.73,0.47) v1(74.27,0.47) v1(76.81,0.47) v1(79.23,0.47) v1(81.77,0.47) v1(84.31,0.47) v1(86.85,0.47) v1(89.64,0.47) v1(92.18,0.47) v1(94.72,0.47) v1(95.1,83.15) v1(97.26,0.47) v1(97.64,83.15) v1(99.67,0.47) v1(100.18,83.15) v1(102.21,0.47) v1(103.13,83.12) v1(104.75,0.47) v1(105.26,83.15) v1(107.29,0.47) v1(107.8,83.15) v1(110.09,0.47) v1(110.34,83.15) v1(112.41,75.43) v1(112.41,5.43) v1(112.6,77.57) v1(112.6,7.57) v1(112.63,0.47) v1(112.88,83.15) v1(113.79,10.91) v1(113.93,73.91) v1(113.93,3.91) v1(114.36,78.8) v1(114.36,8.8) v1(114.53,56.22) v1(114.91,55.38) v1(115.12,53.99) v1(115.17,0.47) v1(115.42,83.15) v1(115.9,56.22) v1(116.07,74.1) v1(116.07,4.1) v1(116.18,54.7) v1(116.43,78.25) v1(116.43,8.25) v1(116.84,10.98) v1(117.07,55.23) v1(117.1,53.71) v1(117.34,6.3) v1(117.48,39.64) v1(117.71,49.16) v1(117.71,0.47) v1(117.78,83.04) v1(117.93,44.49) v1(118.04,15.05) v1(118.87,61.05) v1(119,58.13) v1(119,55.59) v1(119,53.89) v1(119,50.51) v1(119,47.97) v1(119,2.96) v1(119.08,81.19) v1(119.08,78.65) v1(119.1,73.62) v1(119.05,71.08) v1(119.03,65.98) v1(119.03,63.44) v1(119.03,45.35) v1(119.03,42.81) v1(119.03,40.02) v1(119.05,37.53) v1(119.05,34.99) v1(119.05,32.19) v1(119.05,29.65) v1(119.03,27.11) v1(119.03,24.57) v1(119.03,21.78) v1(119.03,19.24) v1(119.13,16.78) v1(119.13,13.47) v1(119.13,10.68) v1(119.13,8.14) v1(119.23,76.16) v1(119.23,68.54) v1(119.23,5.55)
